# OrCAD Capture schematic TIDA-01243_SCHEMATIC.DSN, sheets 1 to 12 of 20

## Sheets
1 PAGE20_PCB_FAB_NOTES: title: TIDA-01243: PCB Fab Notes; rev: 2; company: Texas Instruments, CIS/ICP
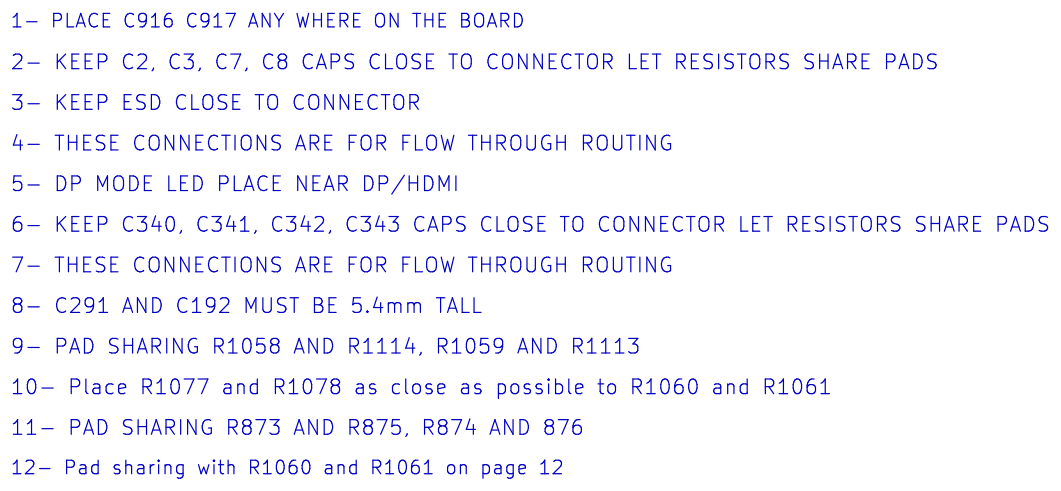
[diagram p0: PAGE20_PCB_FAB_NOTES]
2 PAGE01_EMPTY: title: TIDA-01243 Schematic
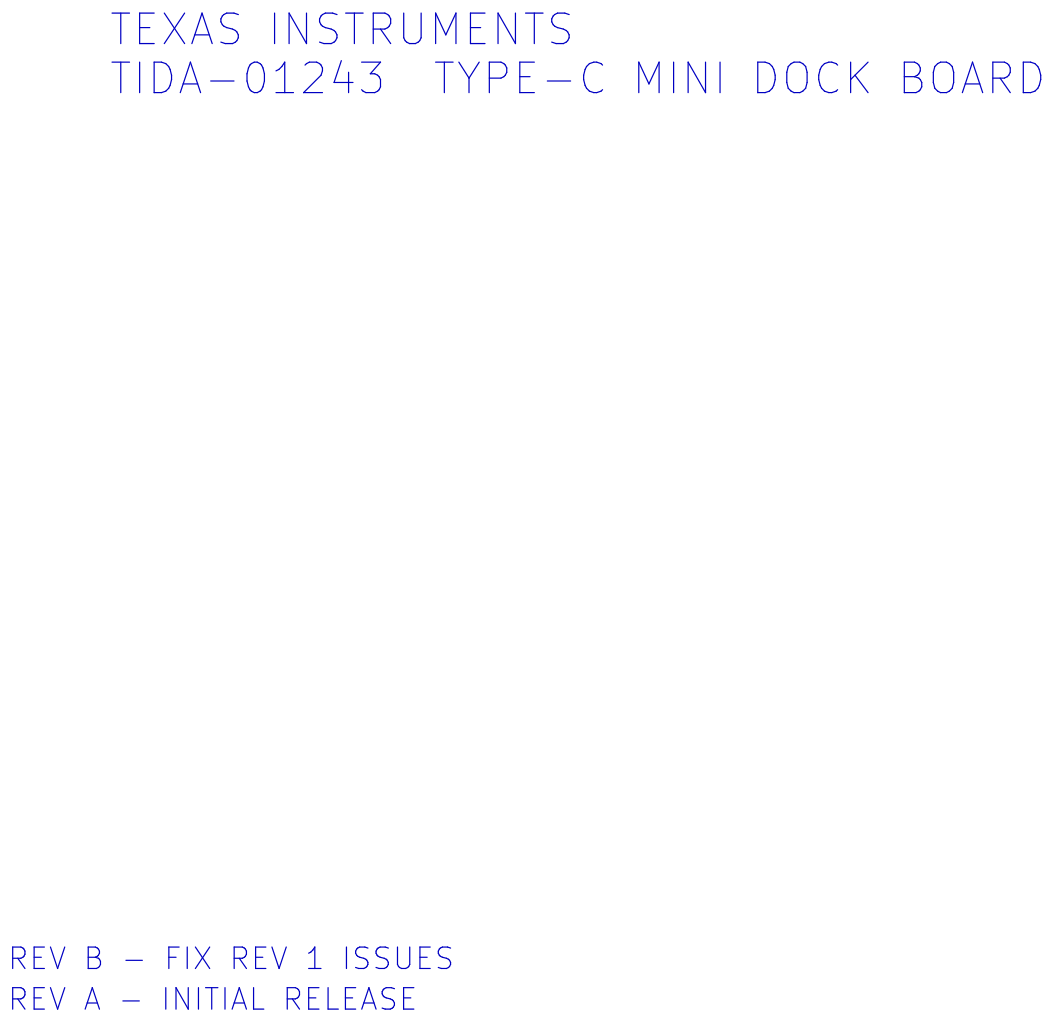
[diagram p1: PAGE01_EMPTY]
3 PAGE02_POWER: size B; title: TIDA-01243: POWER; rev: B
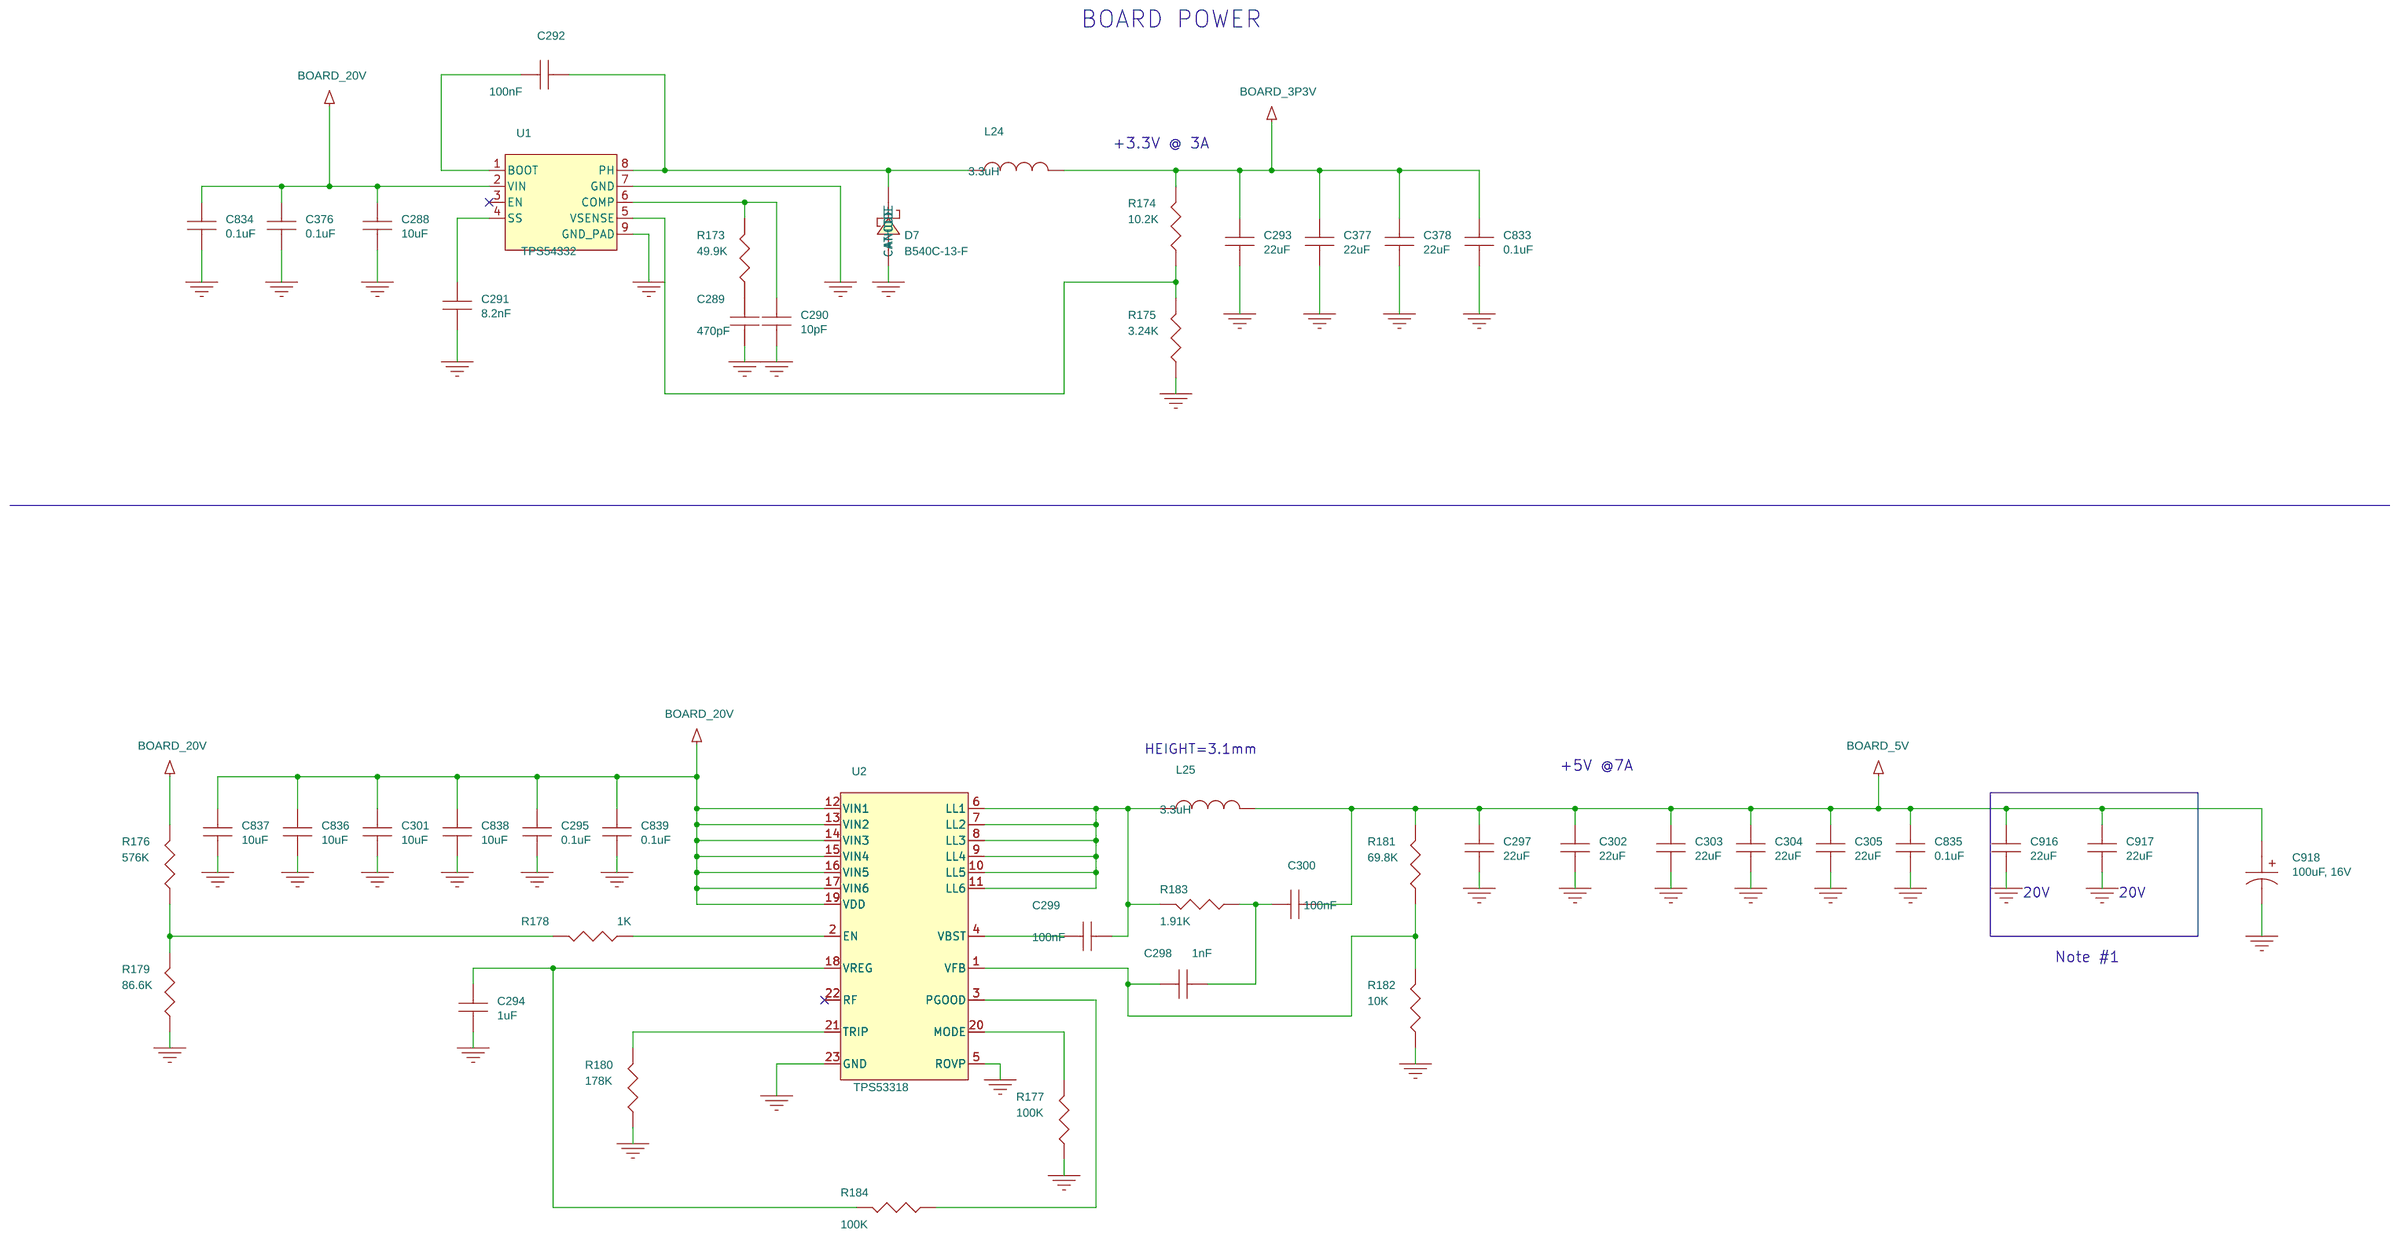
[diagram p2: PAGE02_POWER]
4 PAGE03_POWER2: size B; title: TIDA-01243: POWER2; rev: B
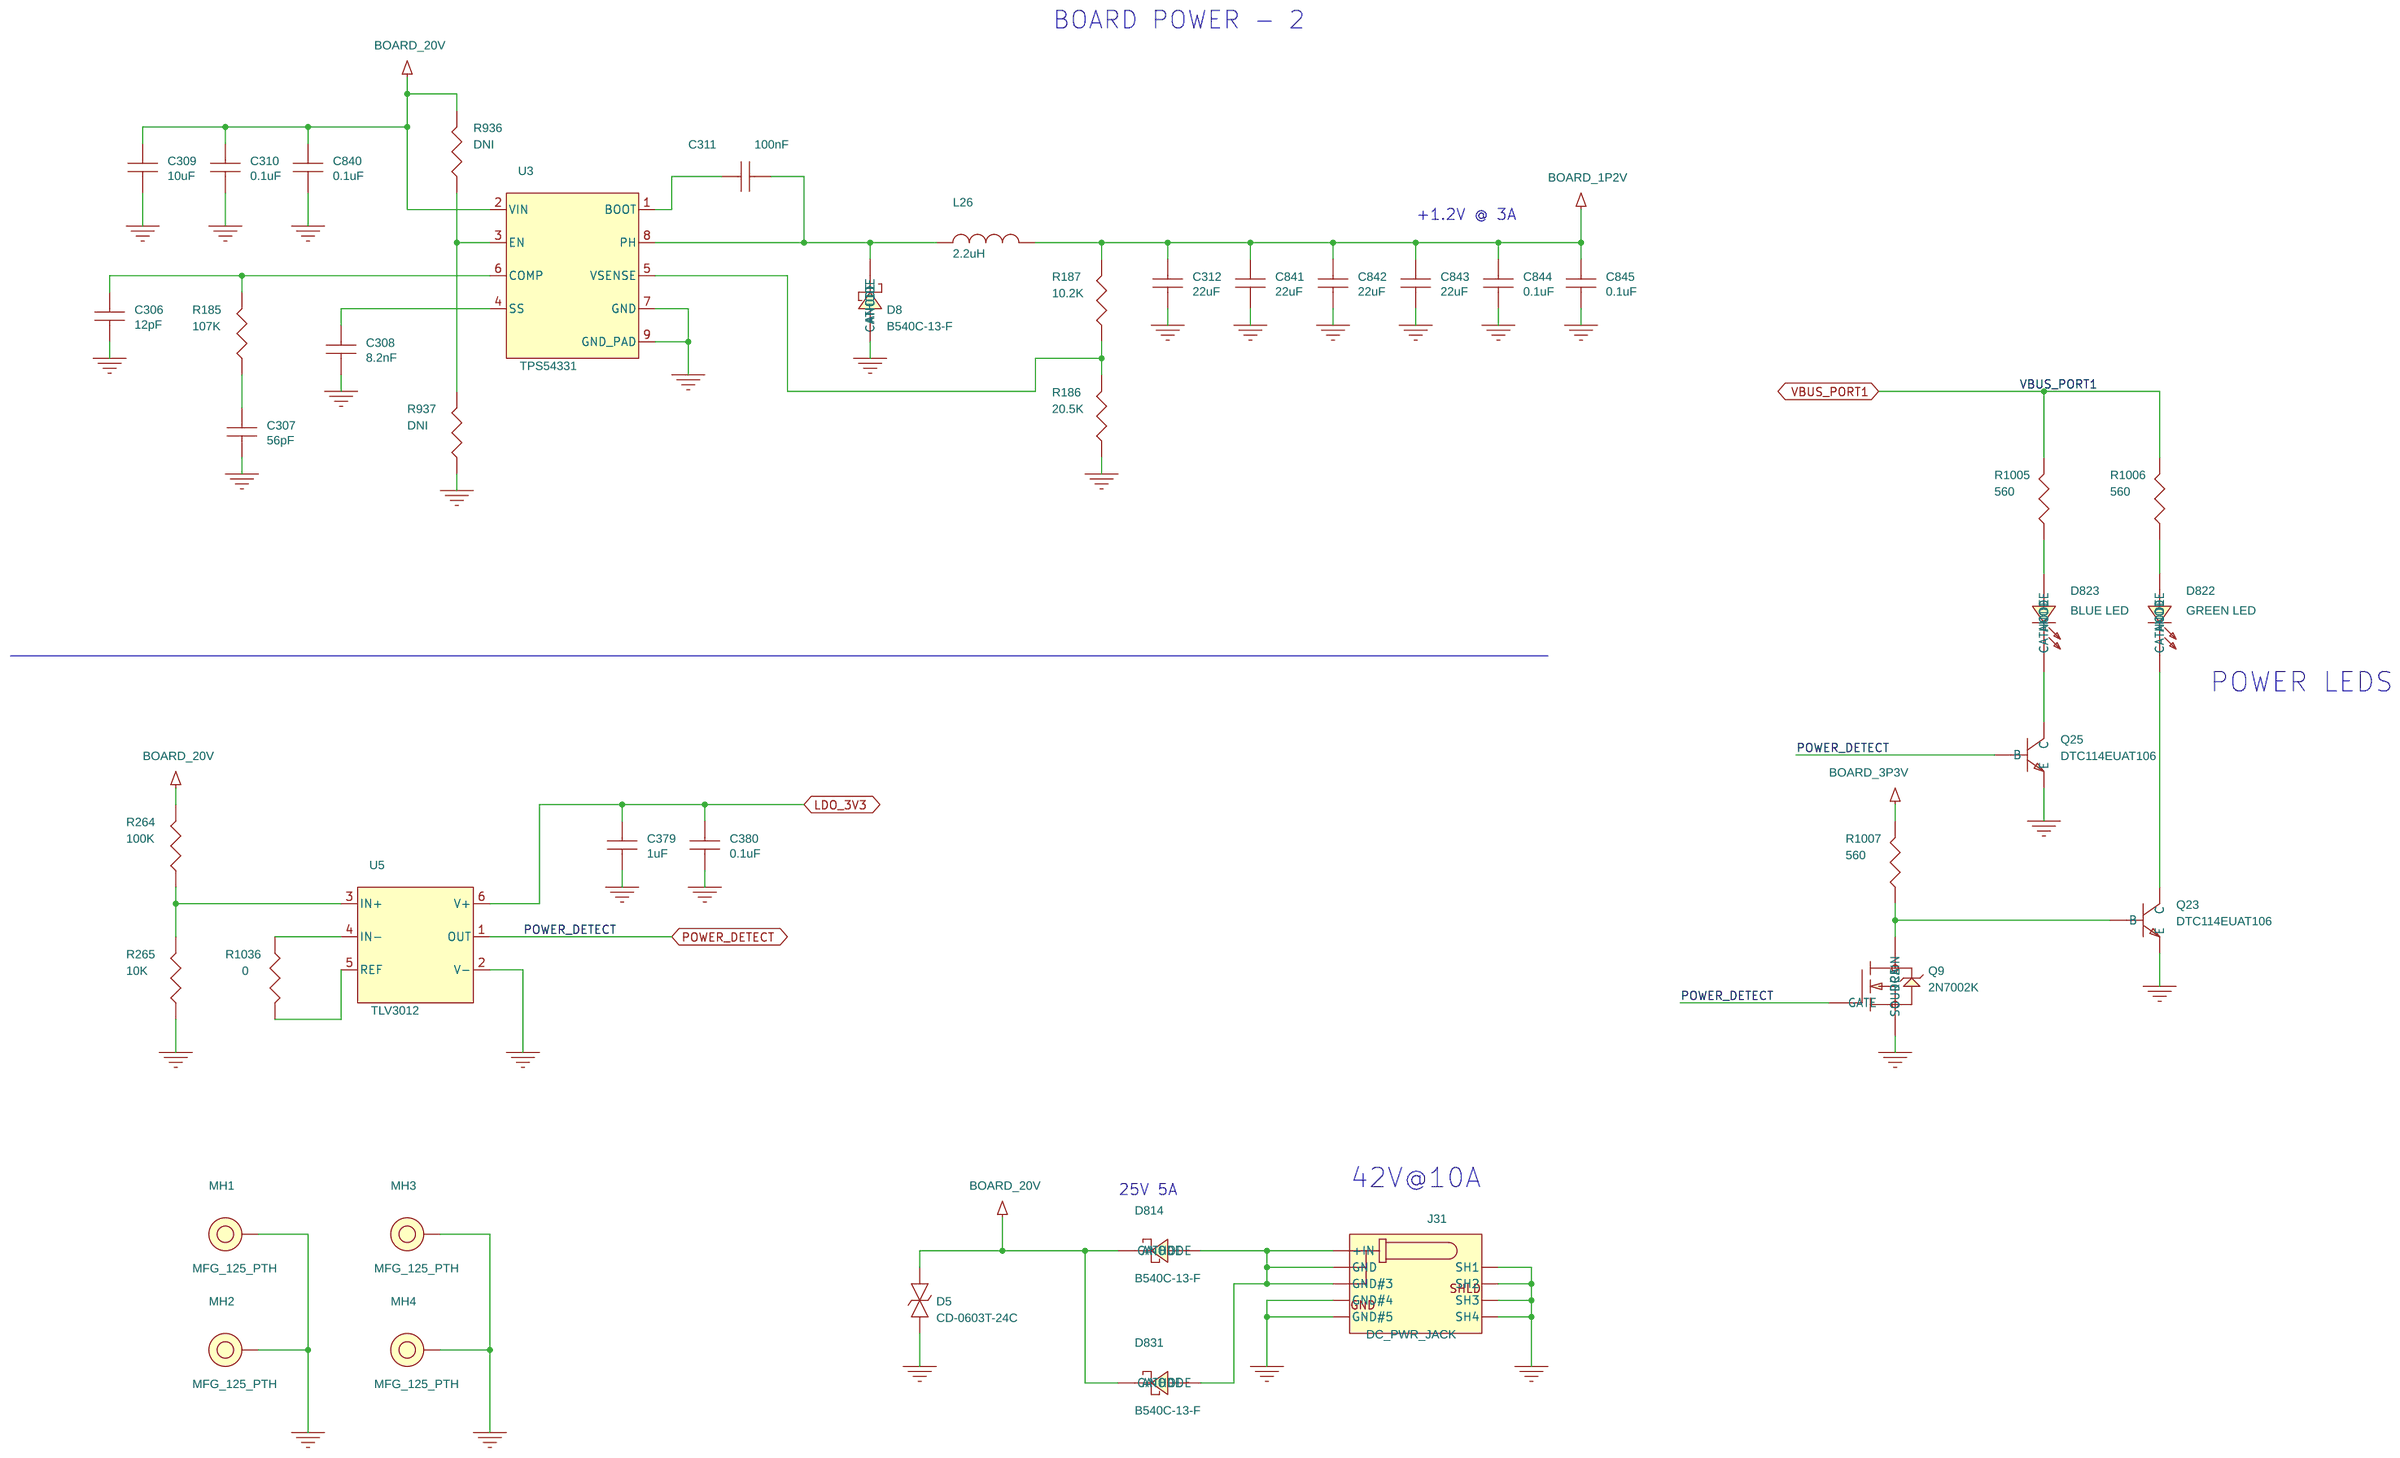
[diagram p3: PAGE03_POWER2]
5 PAGE05_UPSTREAM_TPS65986: size B; title: TIDA-01243: UPSTREAM TPS65986; rev: B
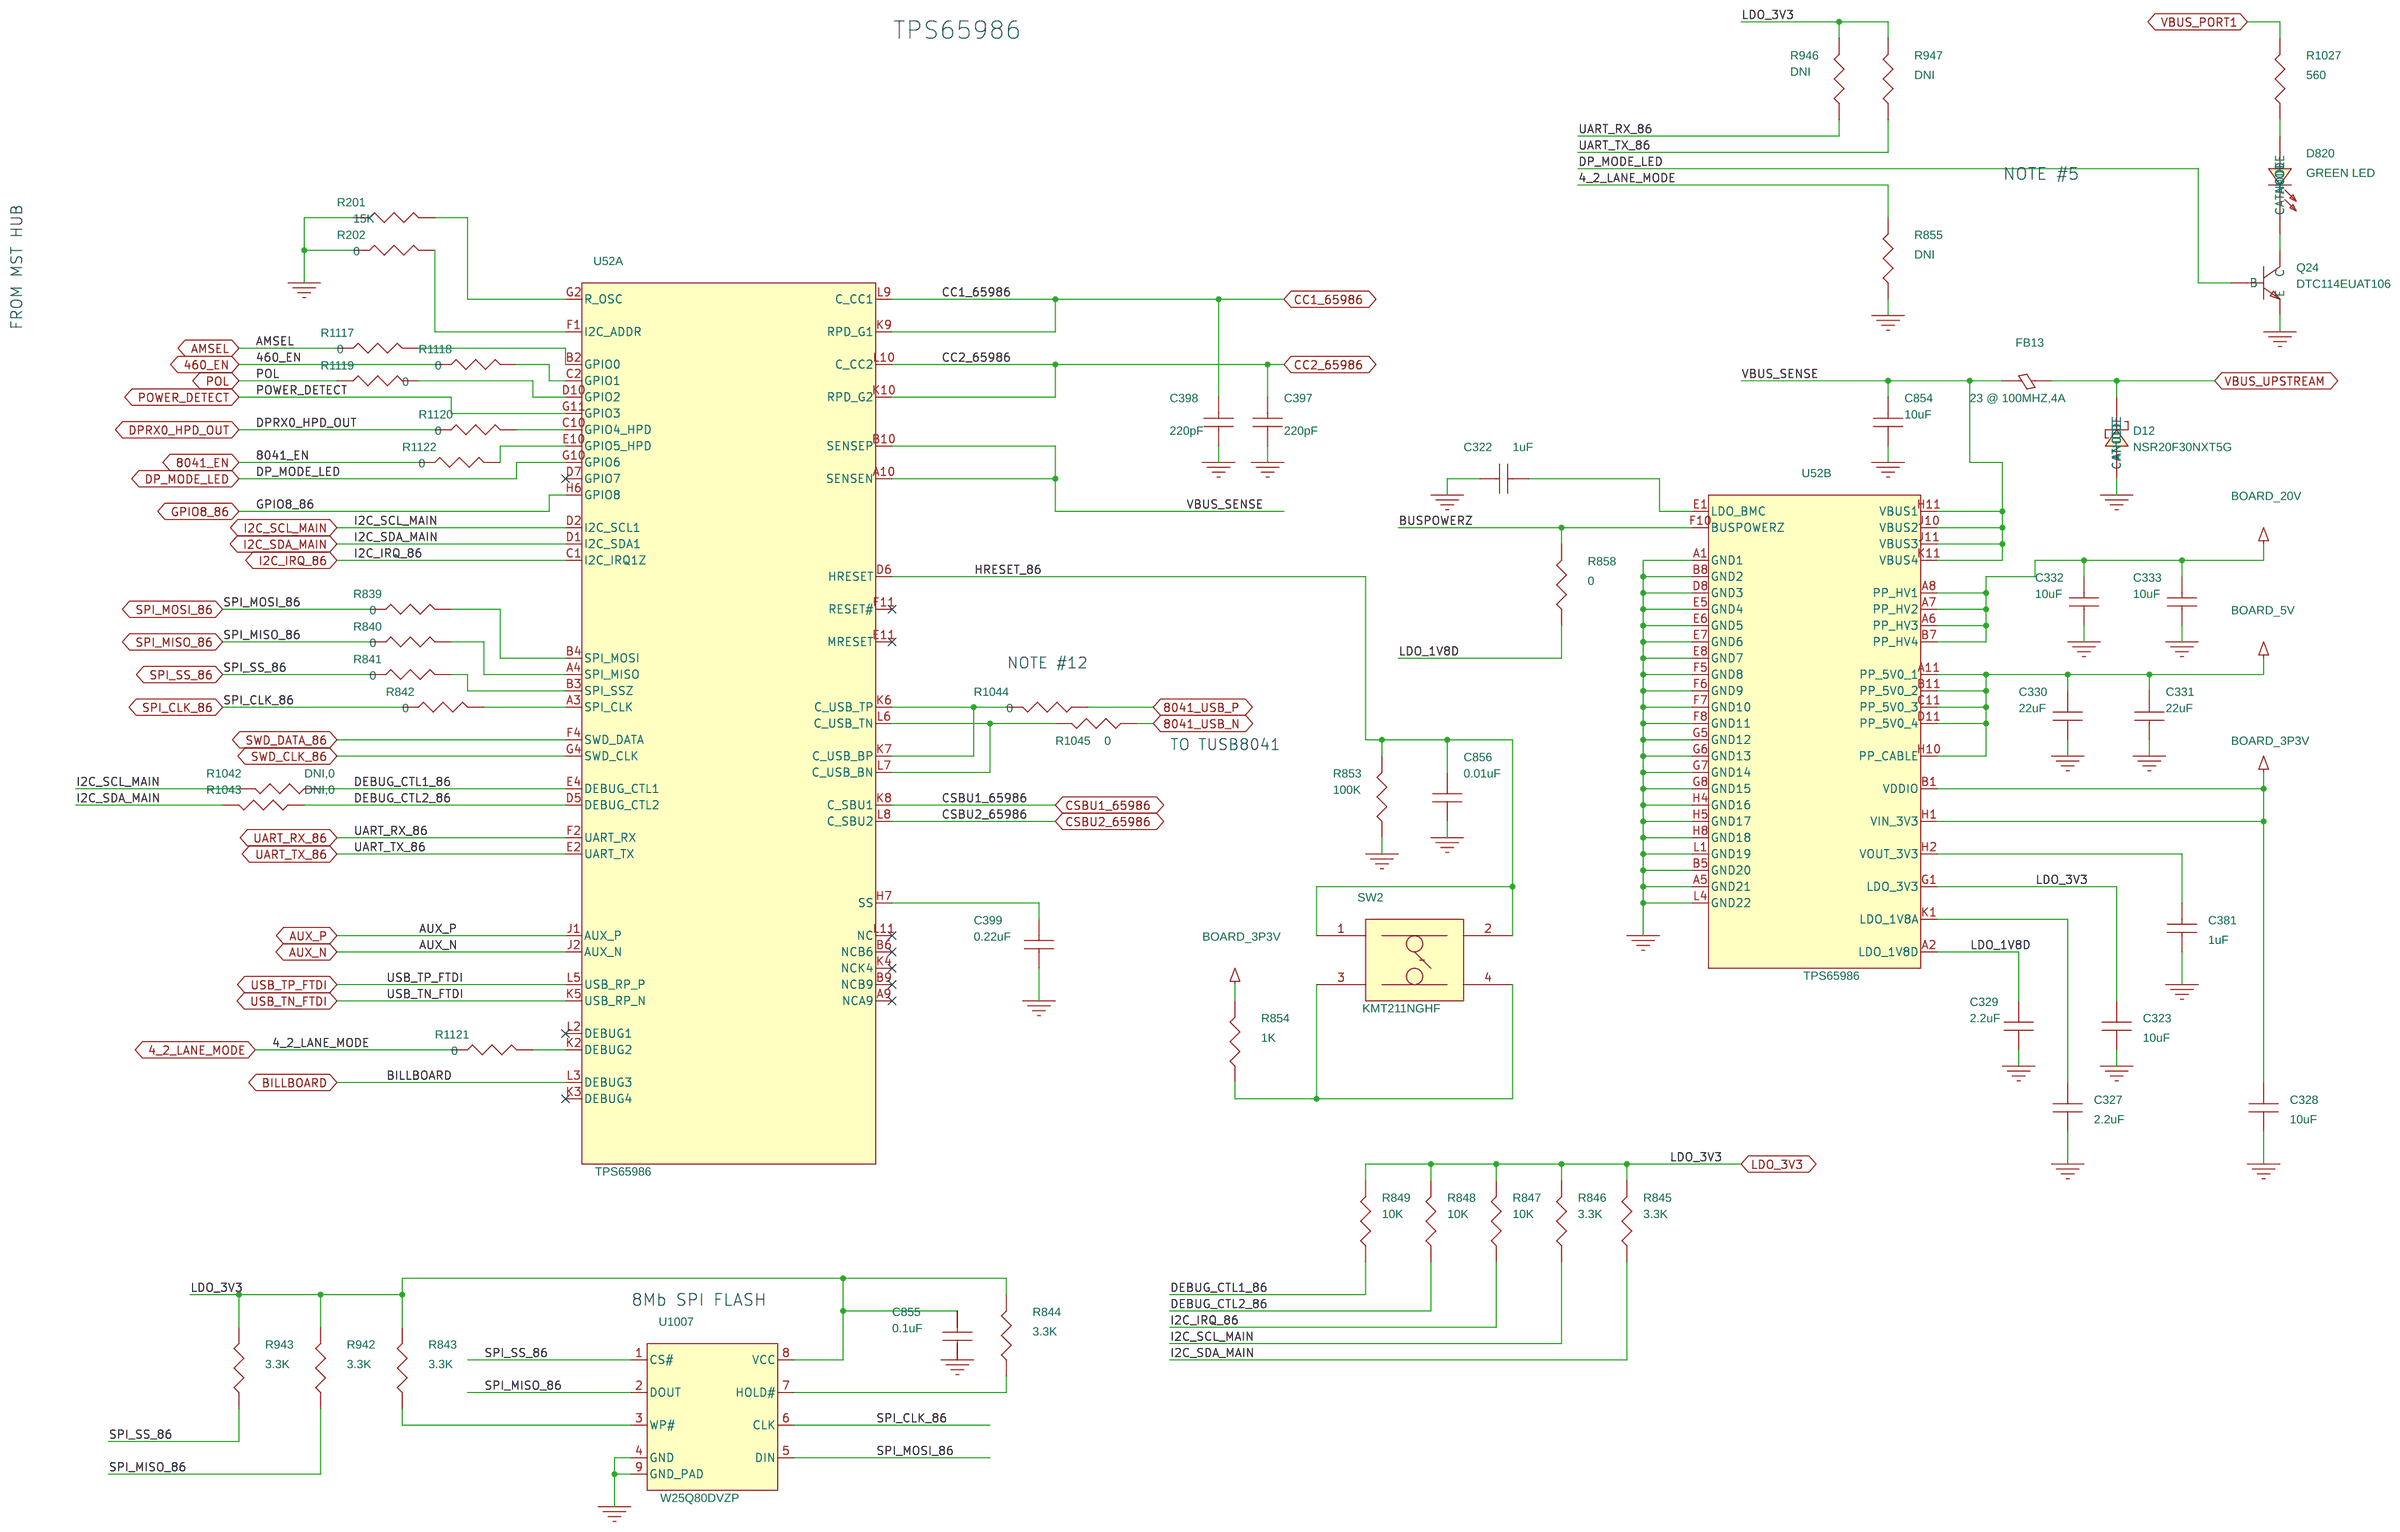
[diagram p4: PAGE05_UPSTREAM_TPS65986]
6 PAGE06_TUSB8041: size B; title: TIDA-01243: TUSB8041; rev: B
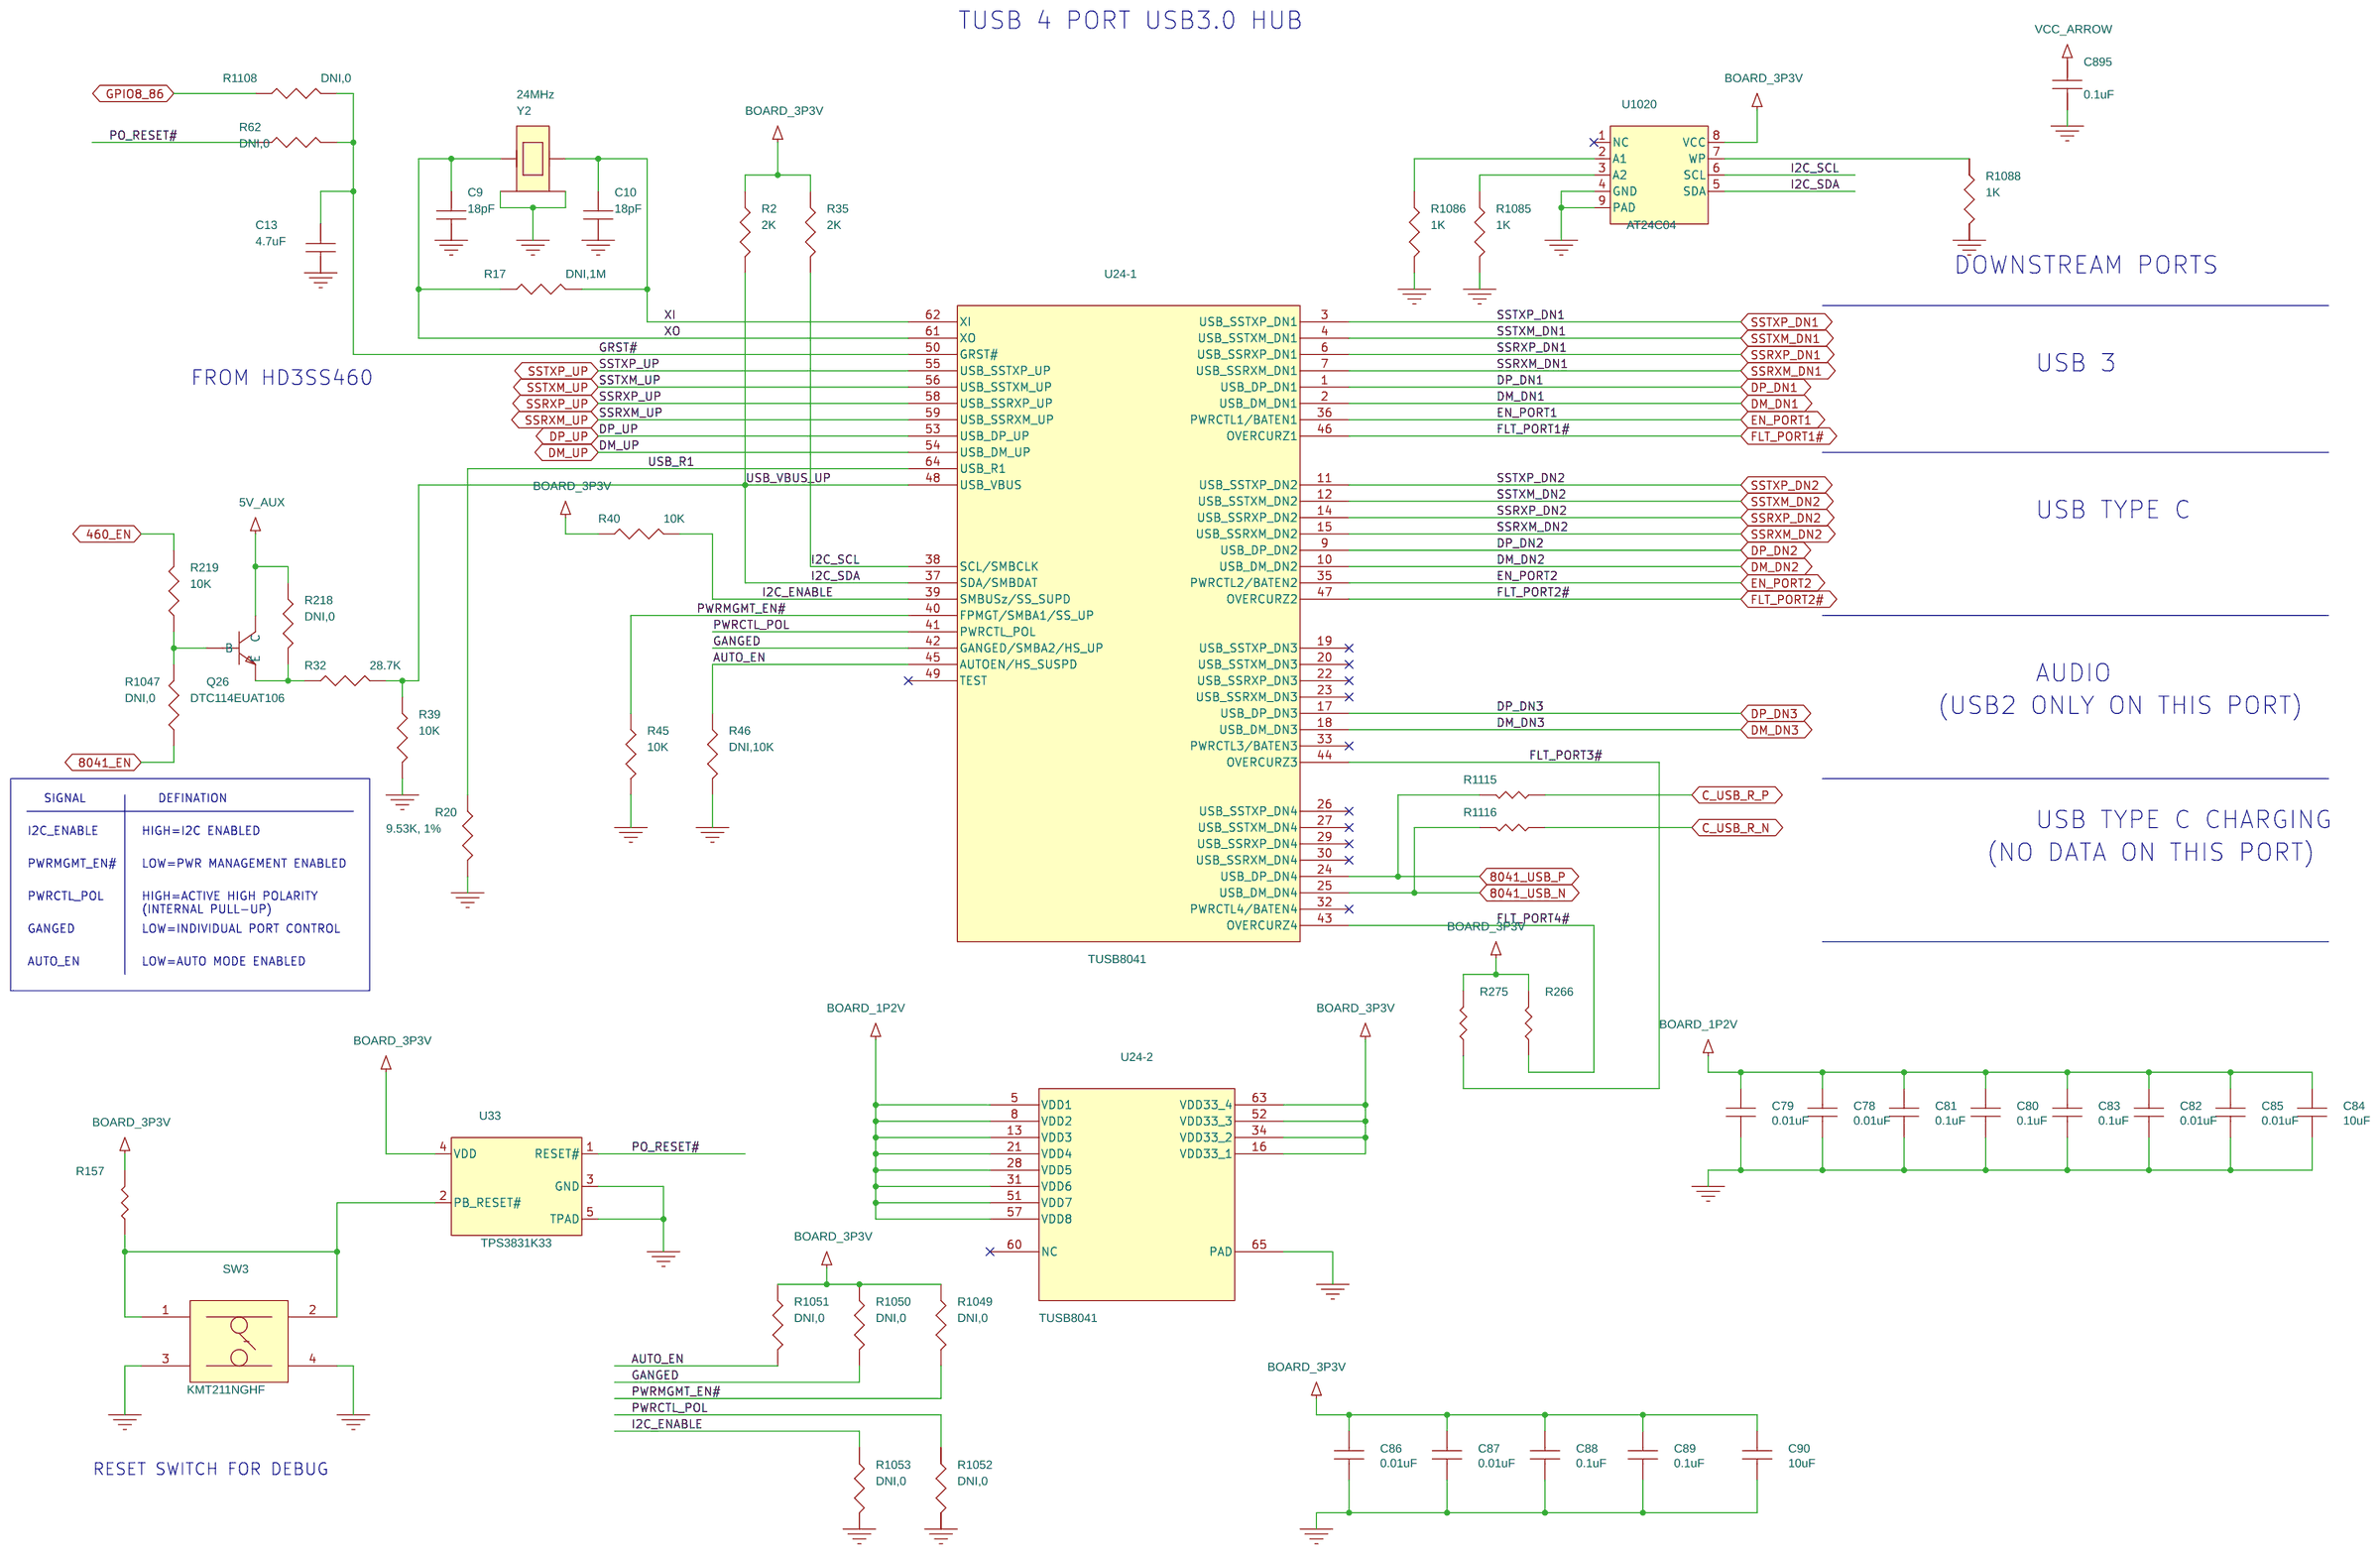
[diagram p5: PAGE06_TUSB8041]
7 PAGE07_PORT1_USB3: size B; title: TIDA-01243: PORT1 USB3; rev: B
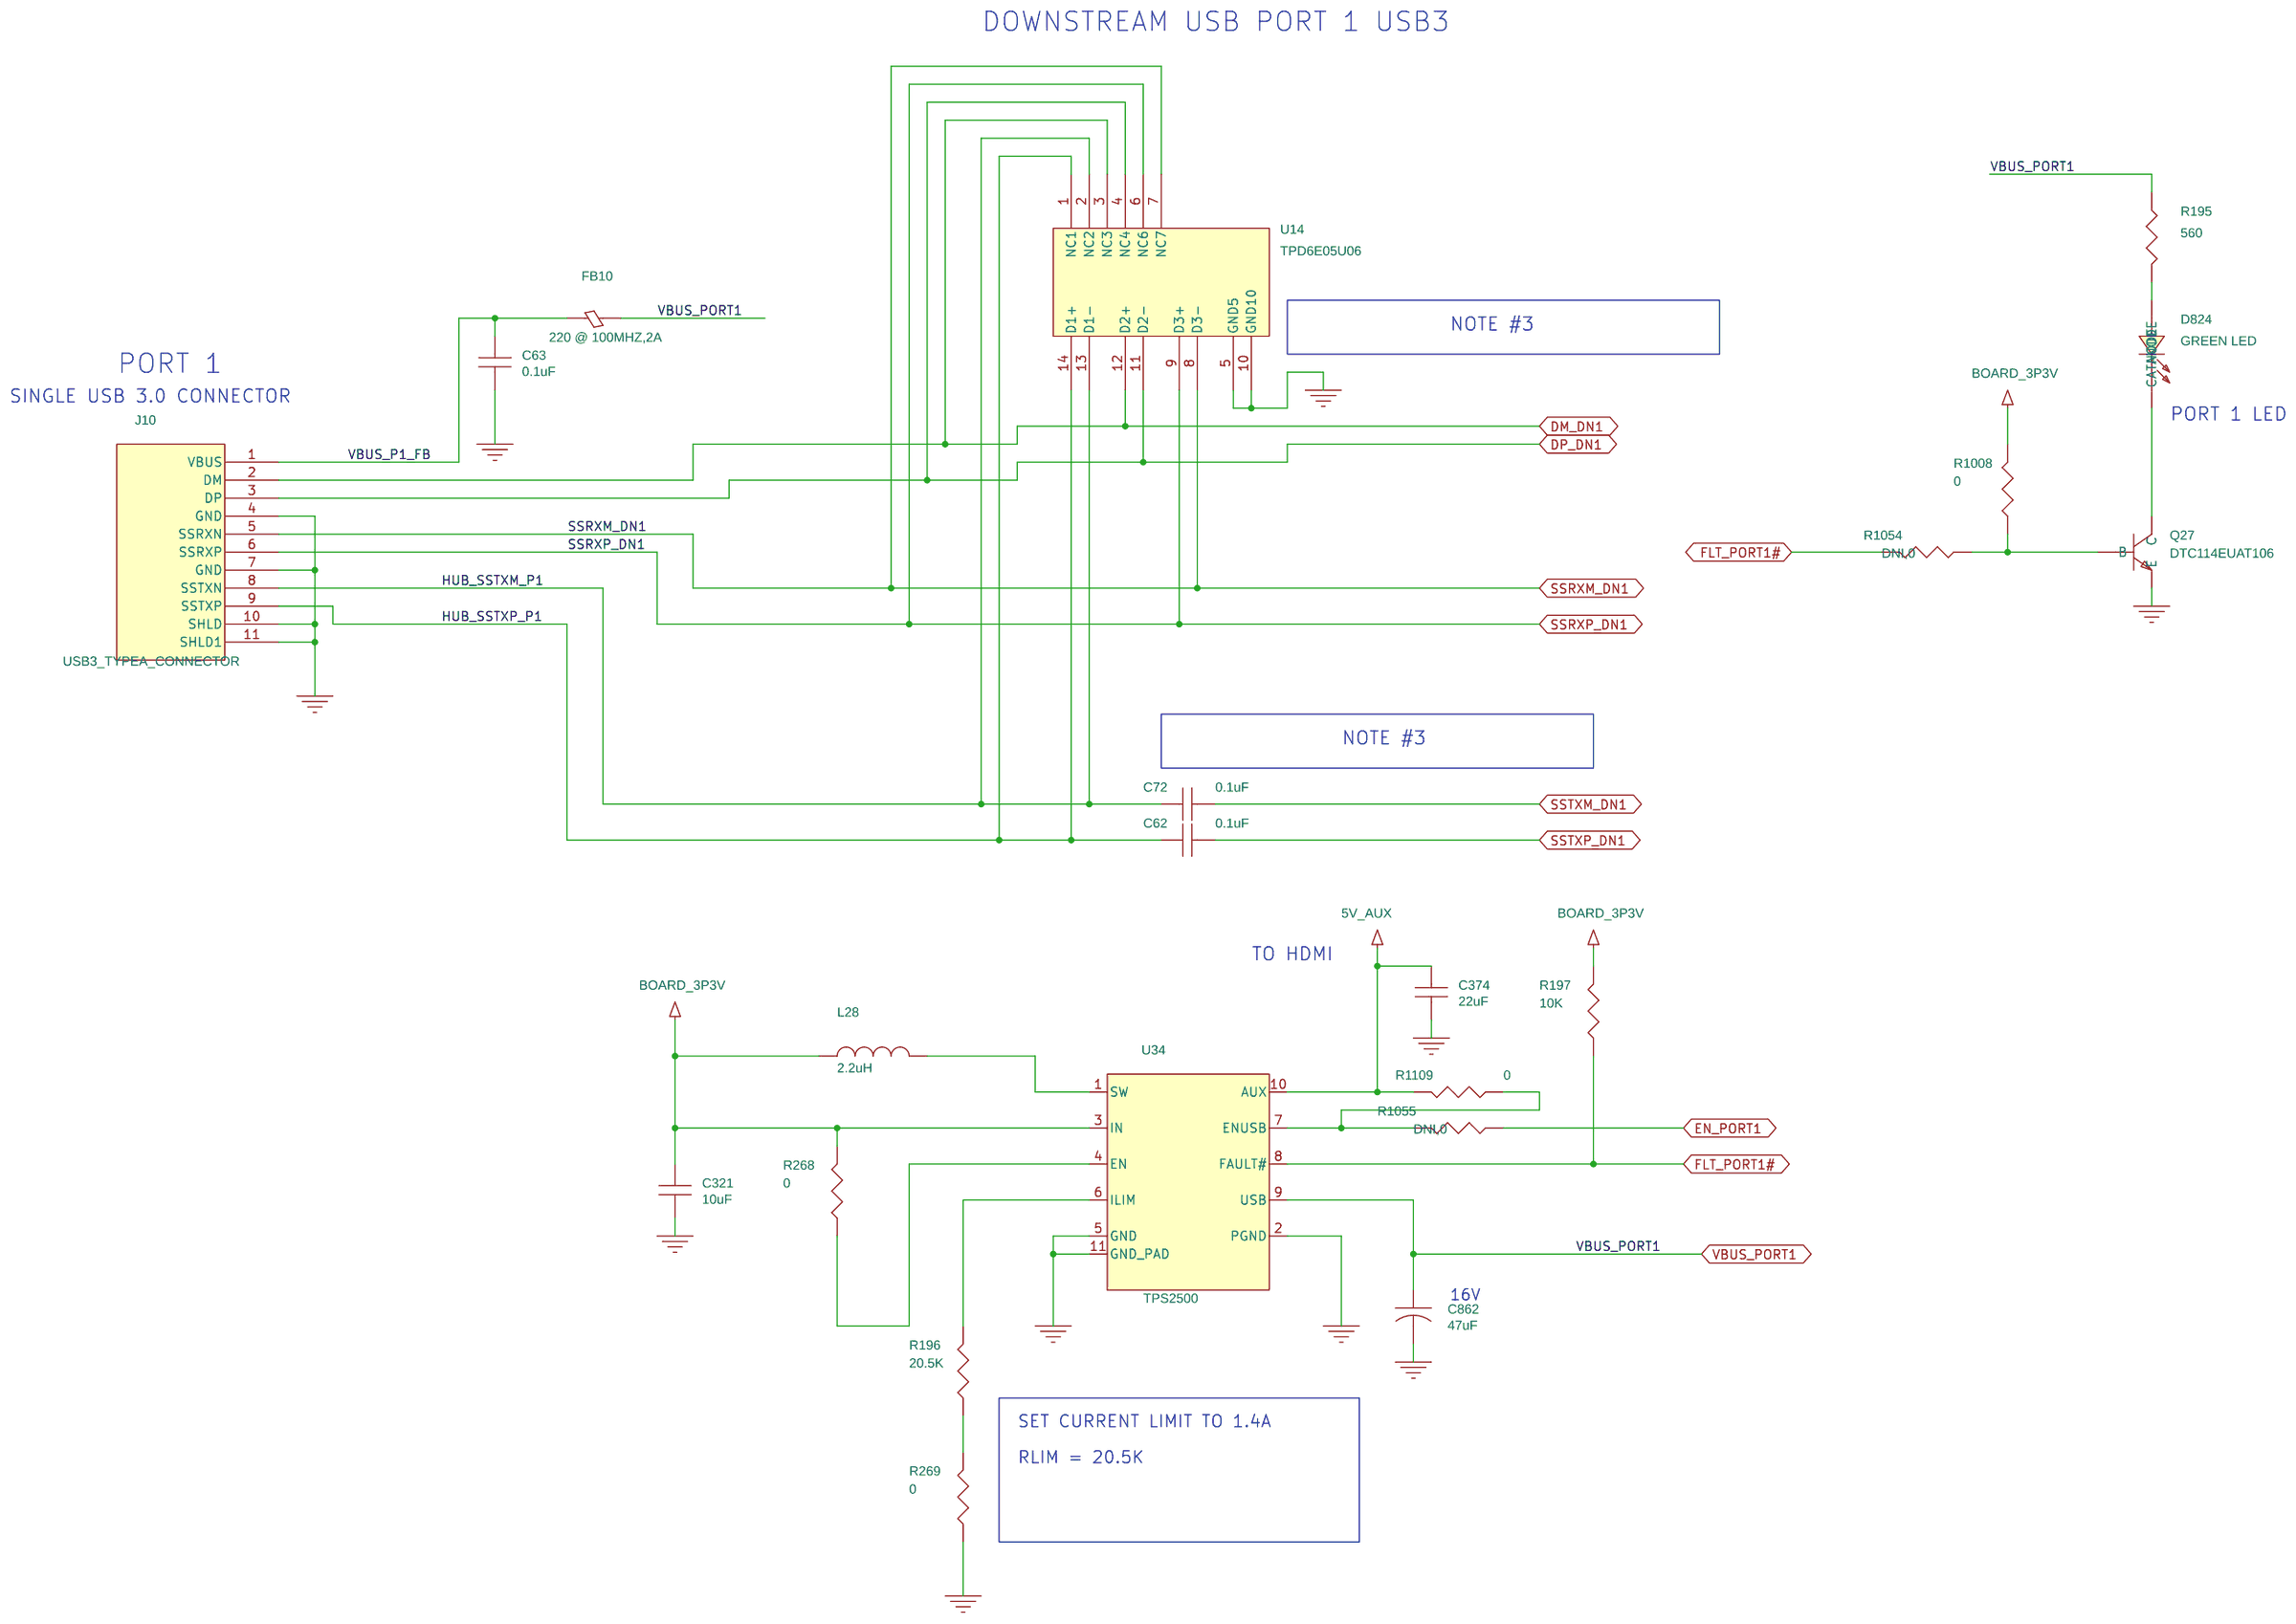
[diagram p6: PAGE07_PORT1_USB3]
8 PAGE08_PORT2_USBC: size B; title: TIDA-01243: PORT 2 USBC; rev: B
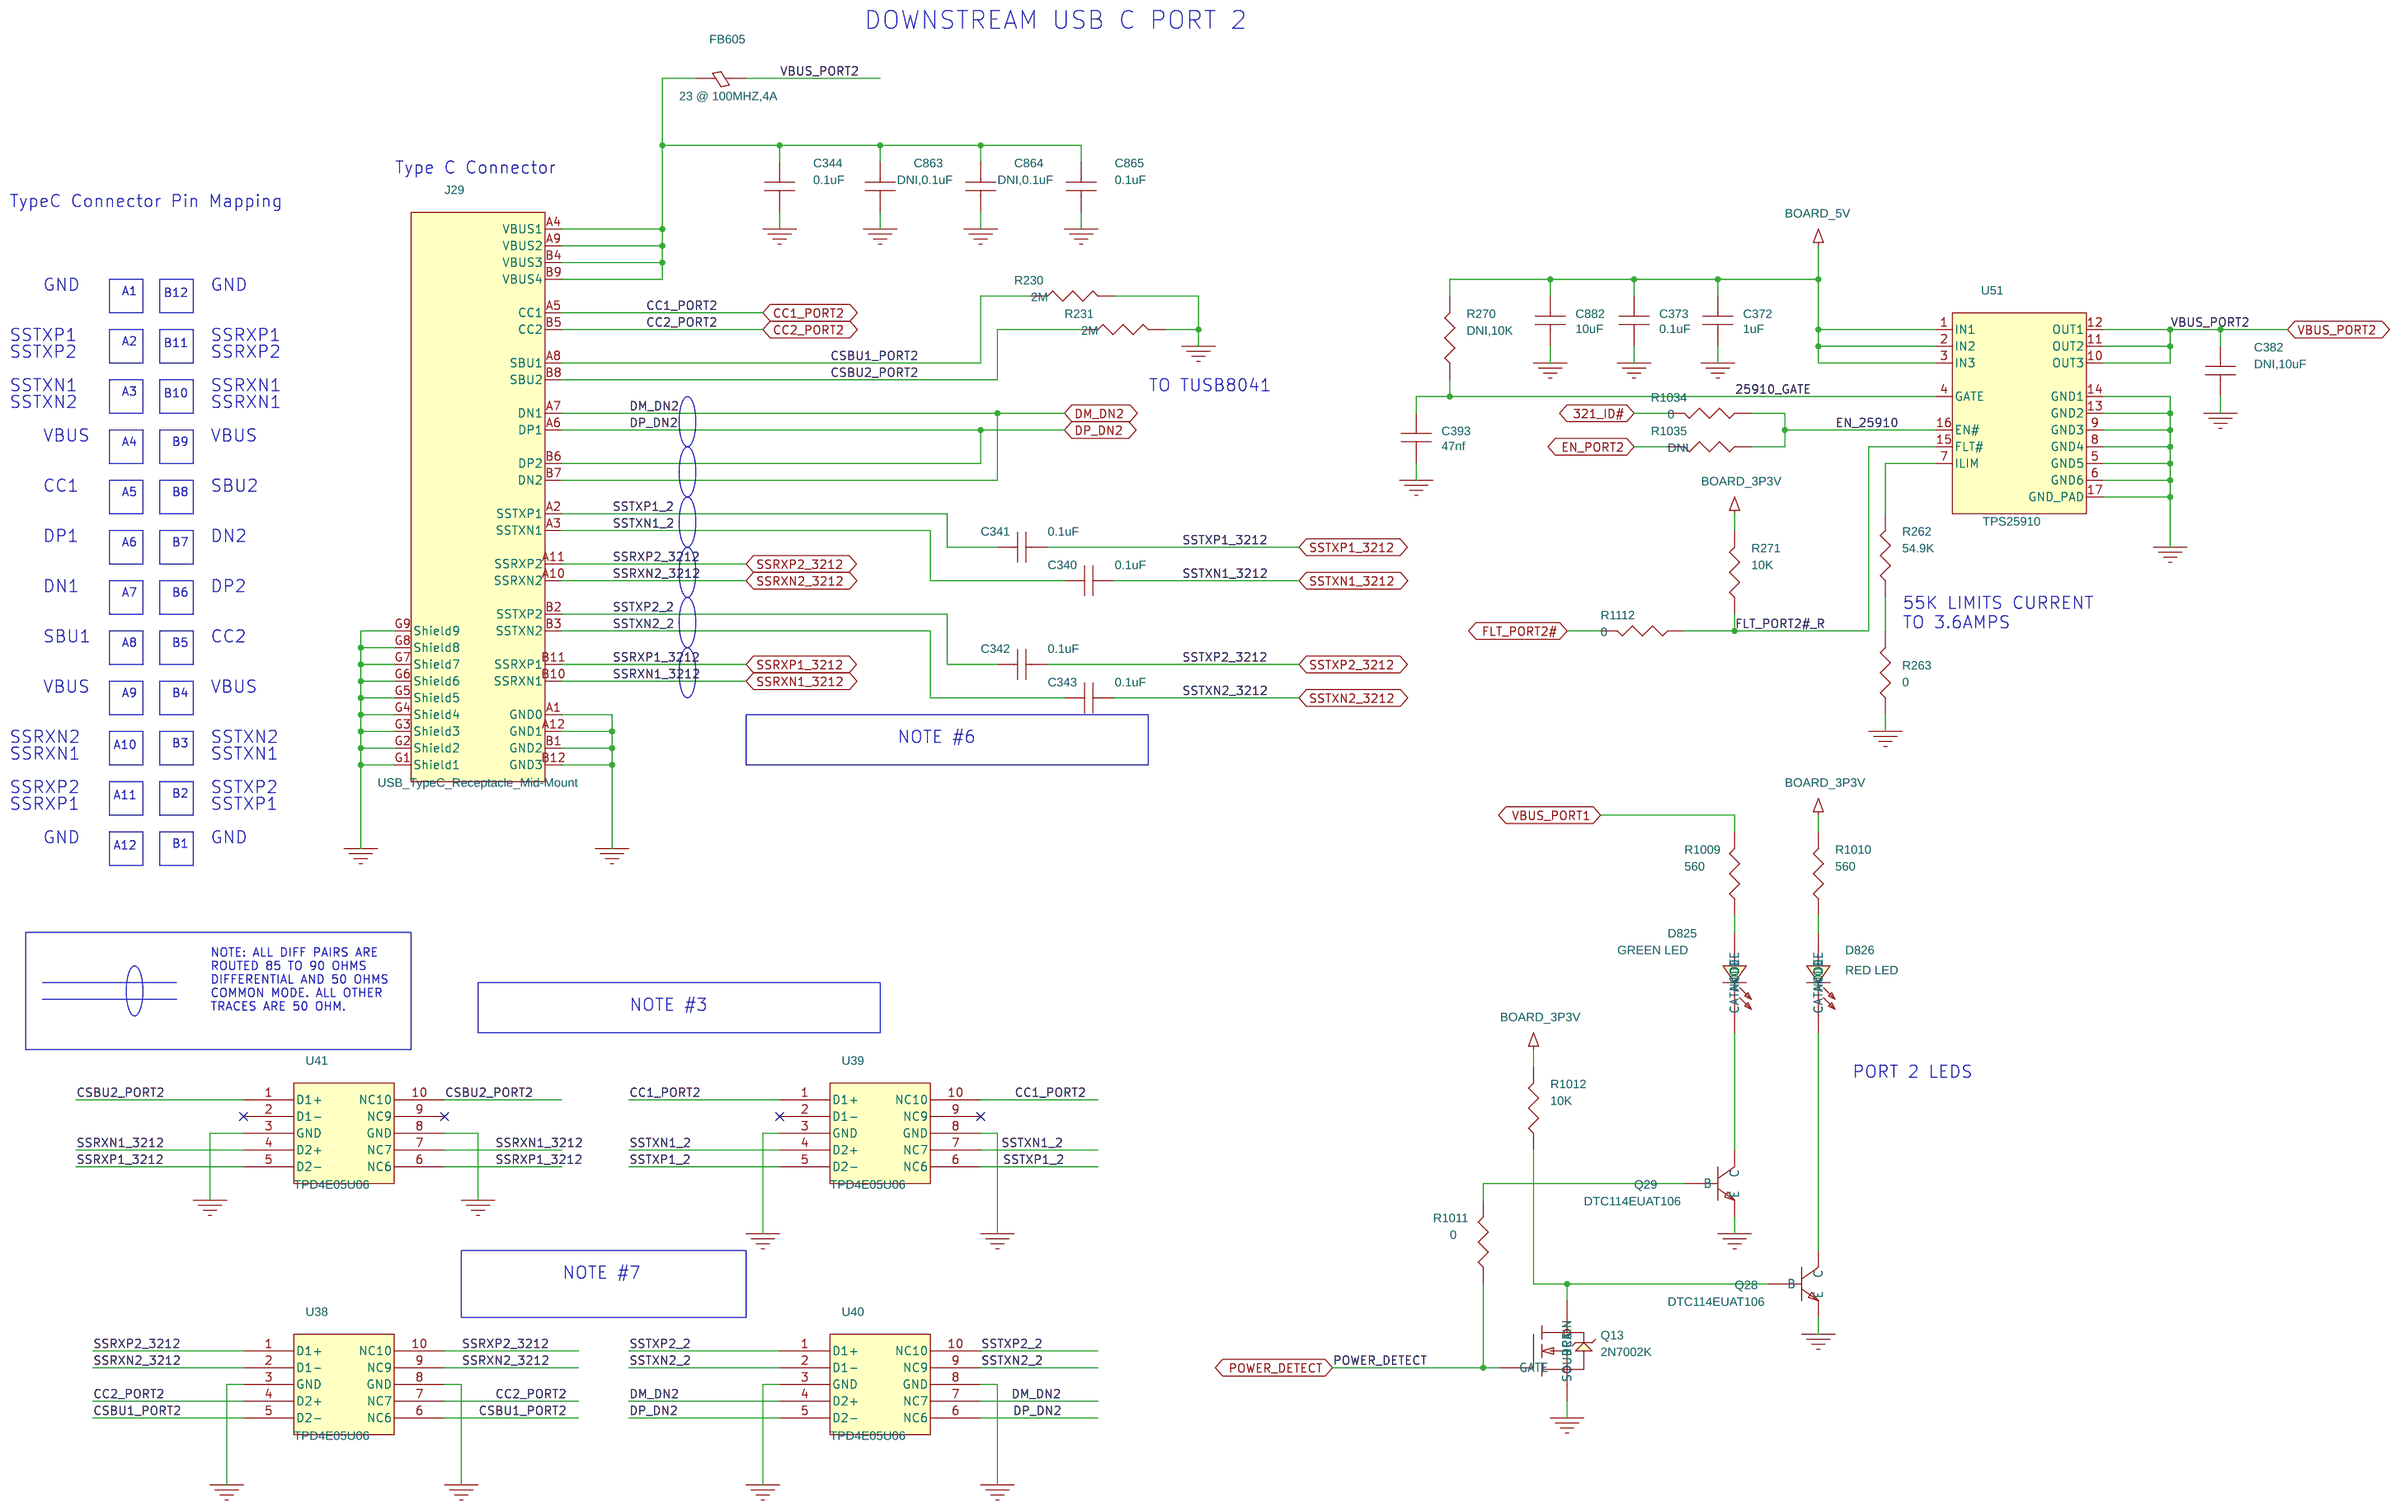
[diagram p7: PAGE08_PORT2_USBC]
9 PAGE09_PORT2_USBC_2: size B; title: TIDA-01243: PORT2_USBC_2; rev: B
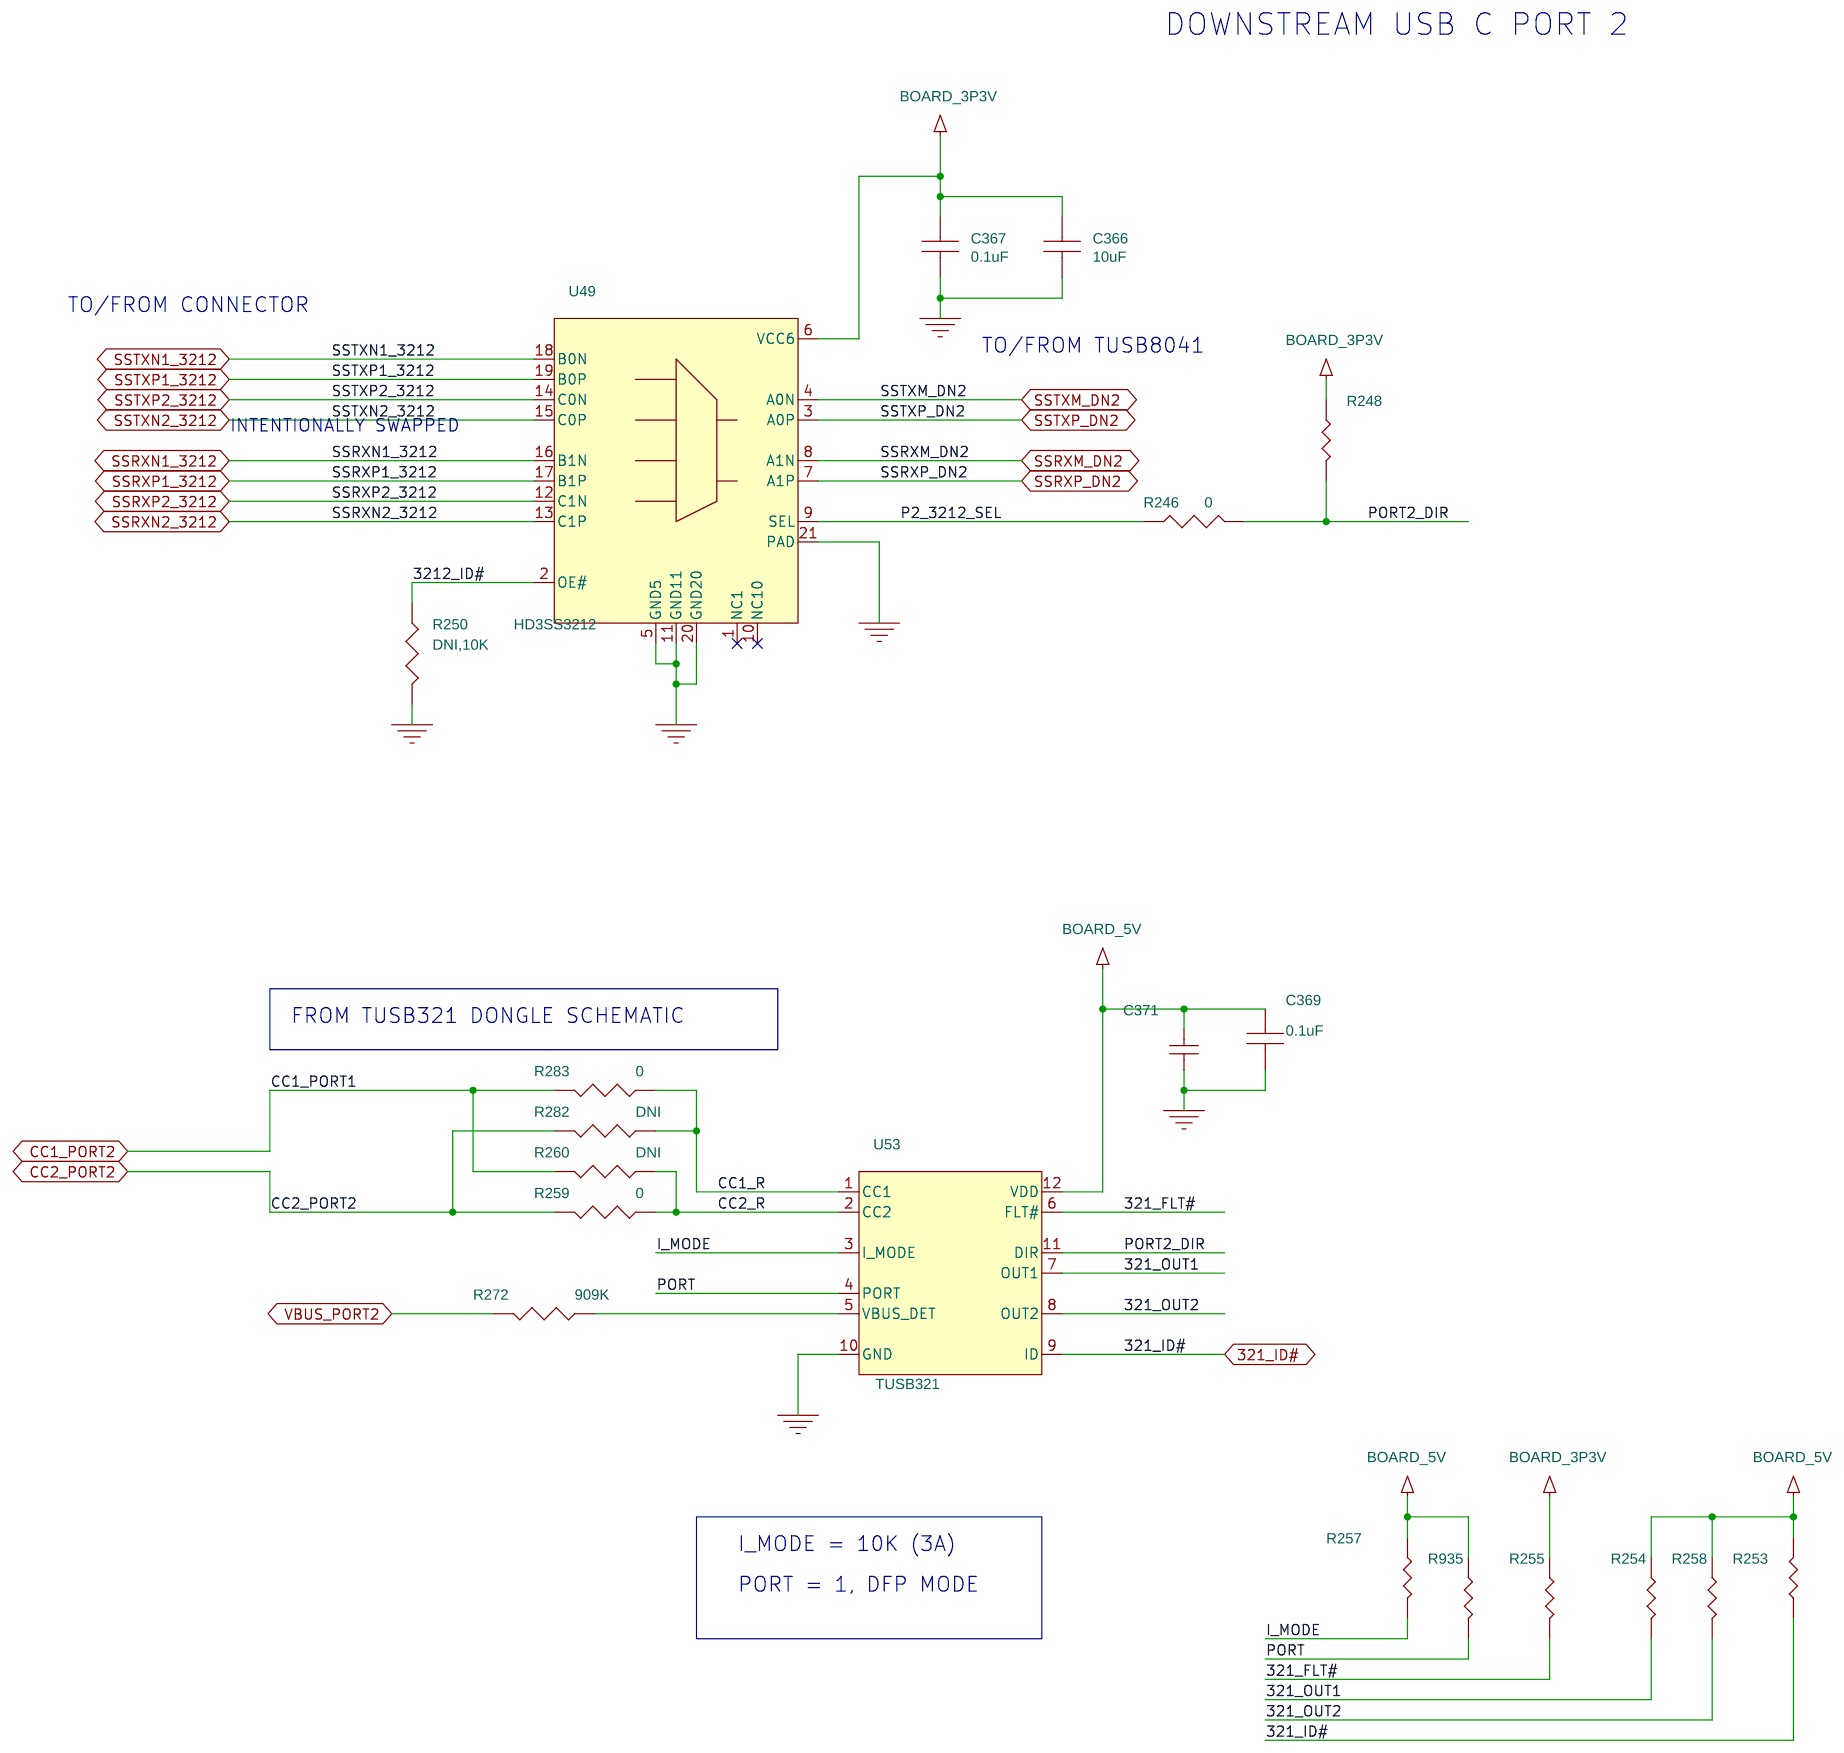
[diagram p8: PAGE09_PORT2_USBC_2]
10 PAGE10_PORT3_USB_AUDIO: size B; title: TIDA-01243: PORT3 USB AUDIO; rev: B
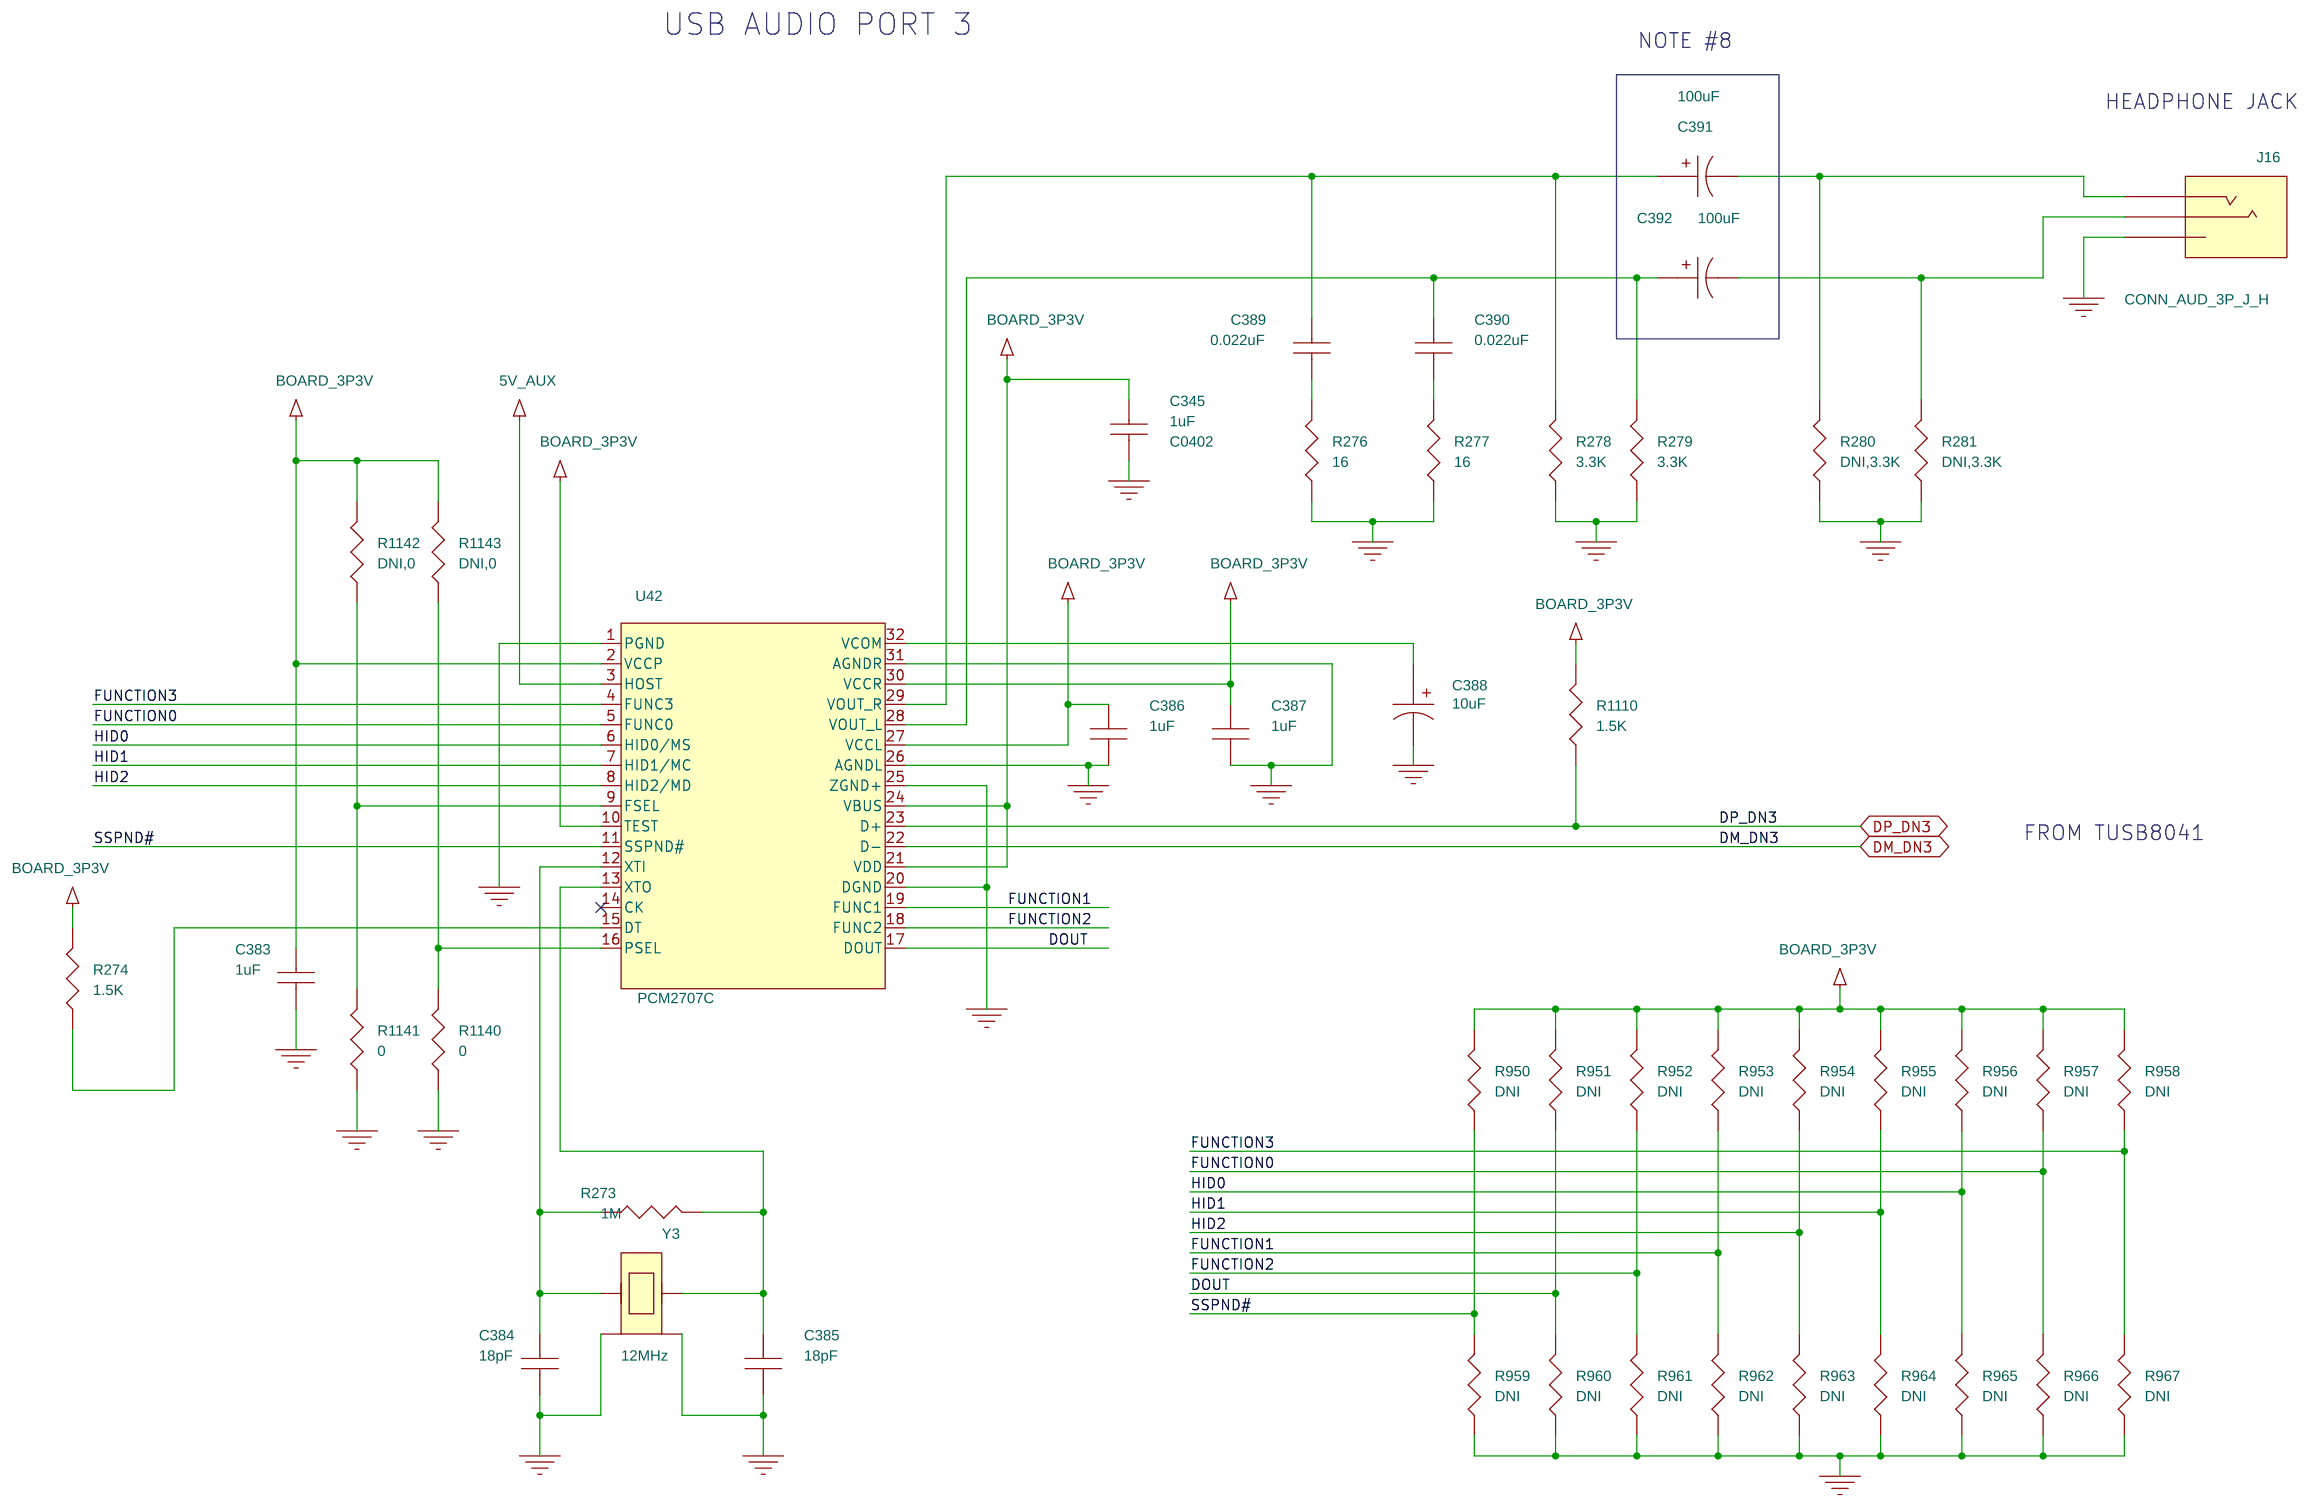
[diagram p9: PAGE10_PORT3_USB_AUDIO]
11 PAGE11_PORT4_USB_C_CHARGING: size B; title: TIDA-01243: PORT4_USBC_CHARGING; rev: B
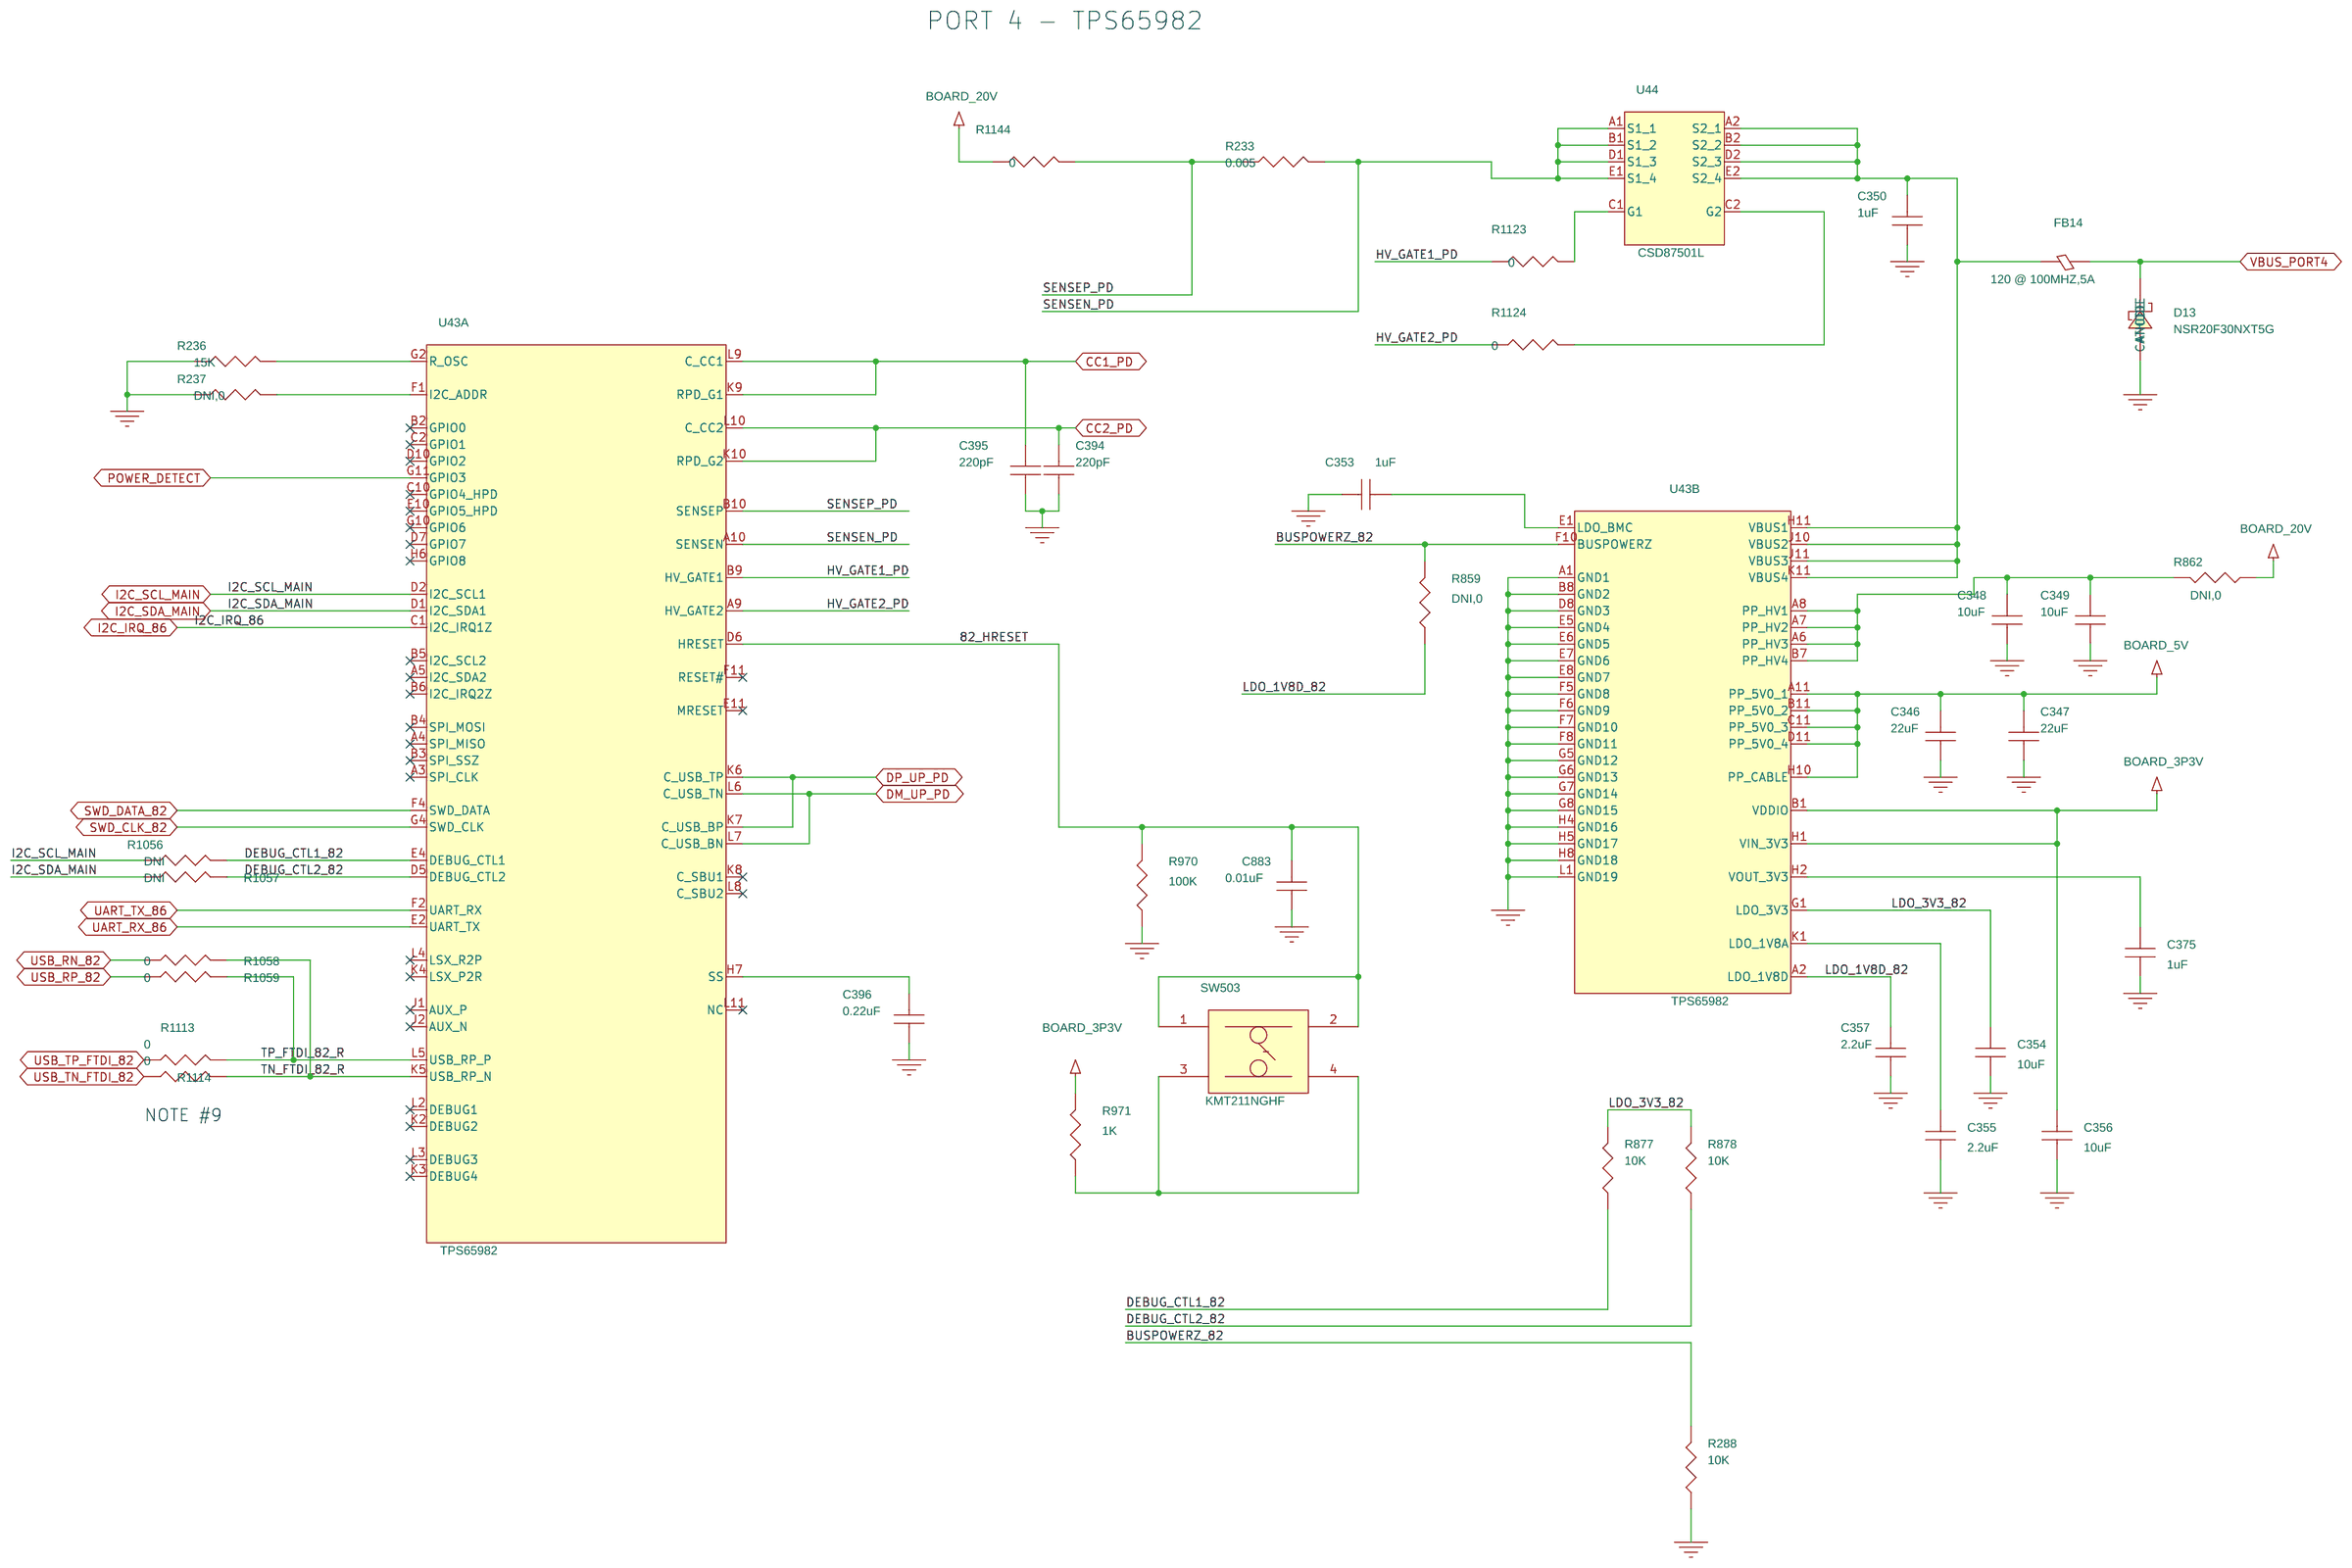
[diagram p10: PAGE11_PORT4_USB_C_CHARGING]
12 PAGE12_PORT4_USB_C_CON: size B; title: TIDA-01243: PORT4 USBC CON; rev: B
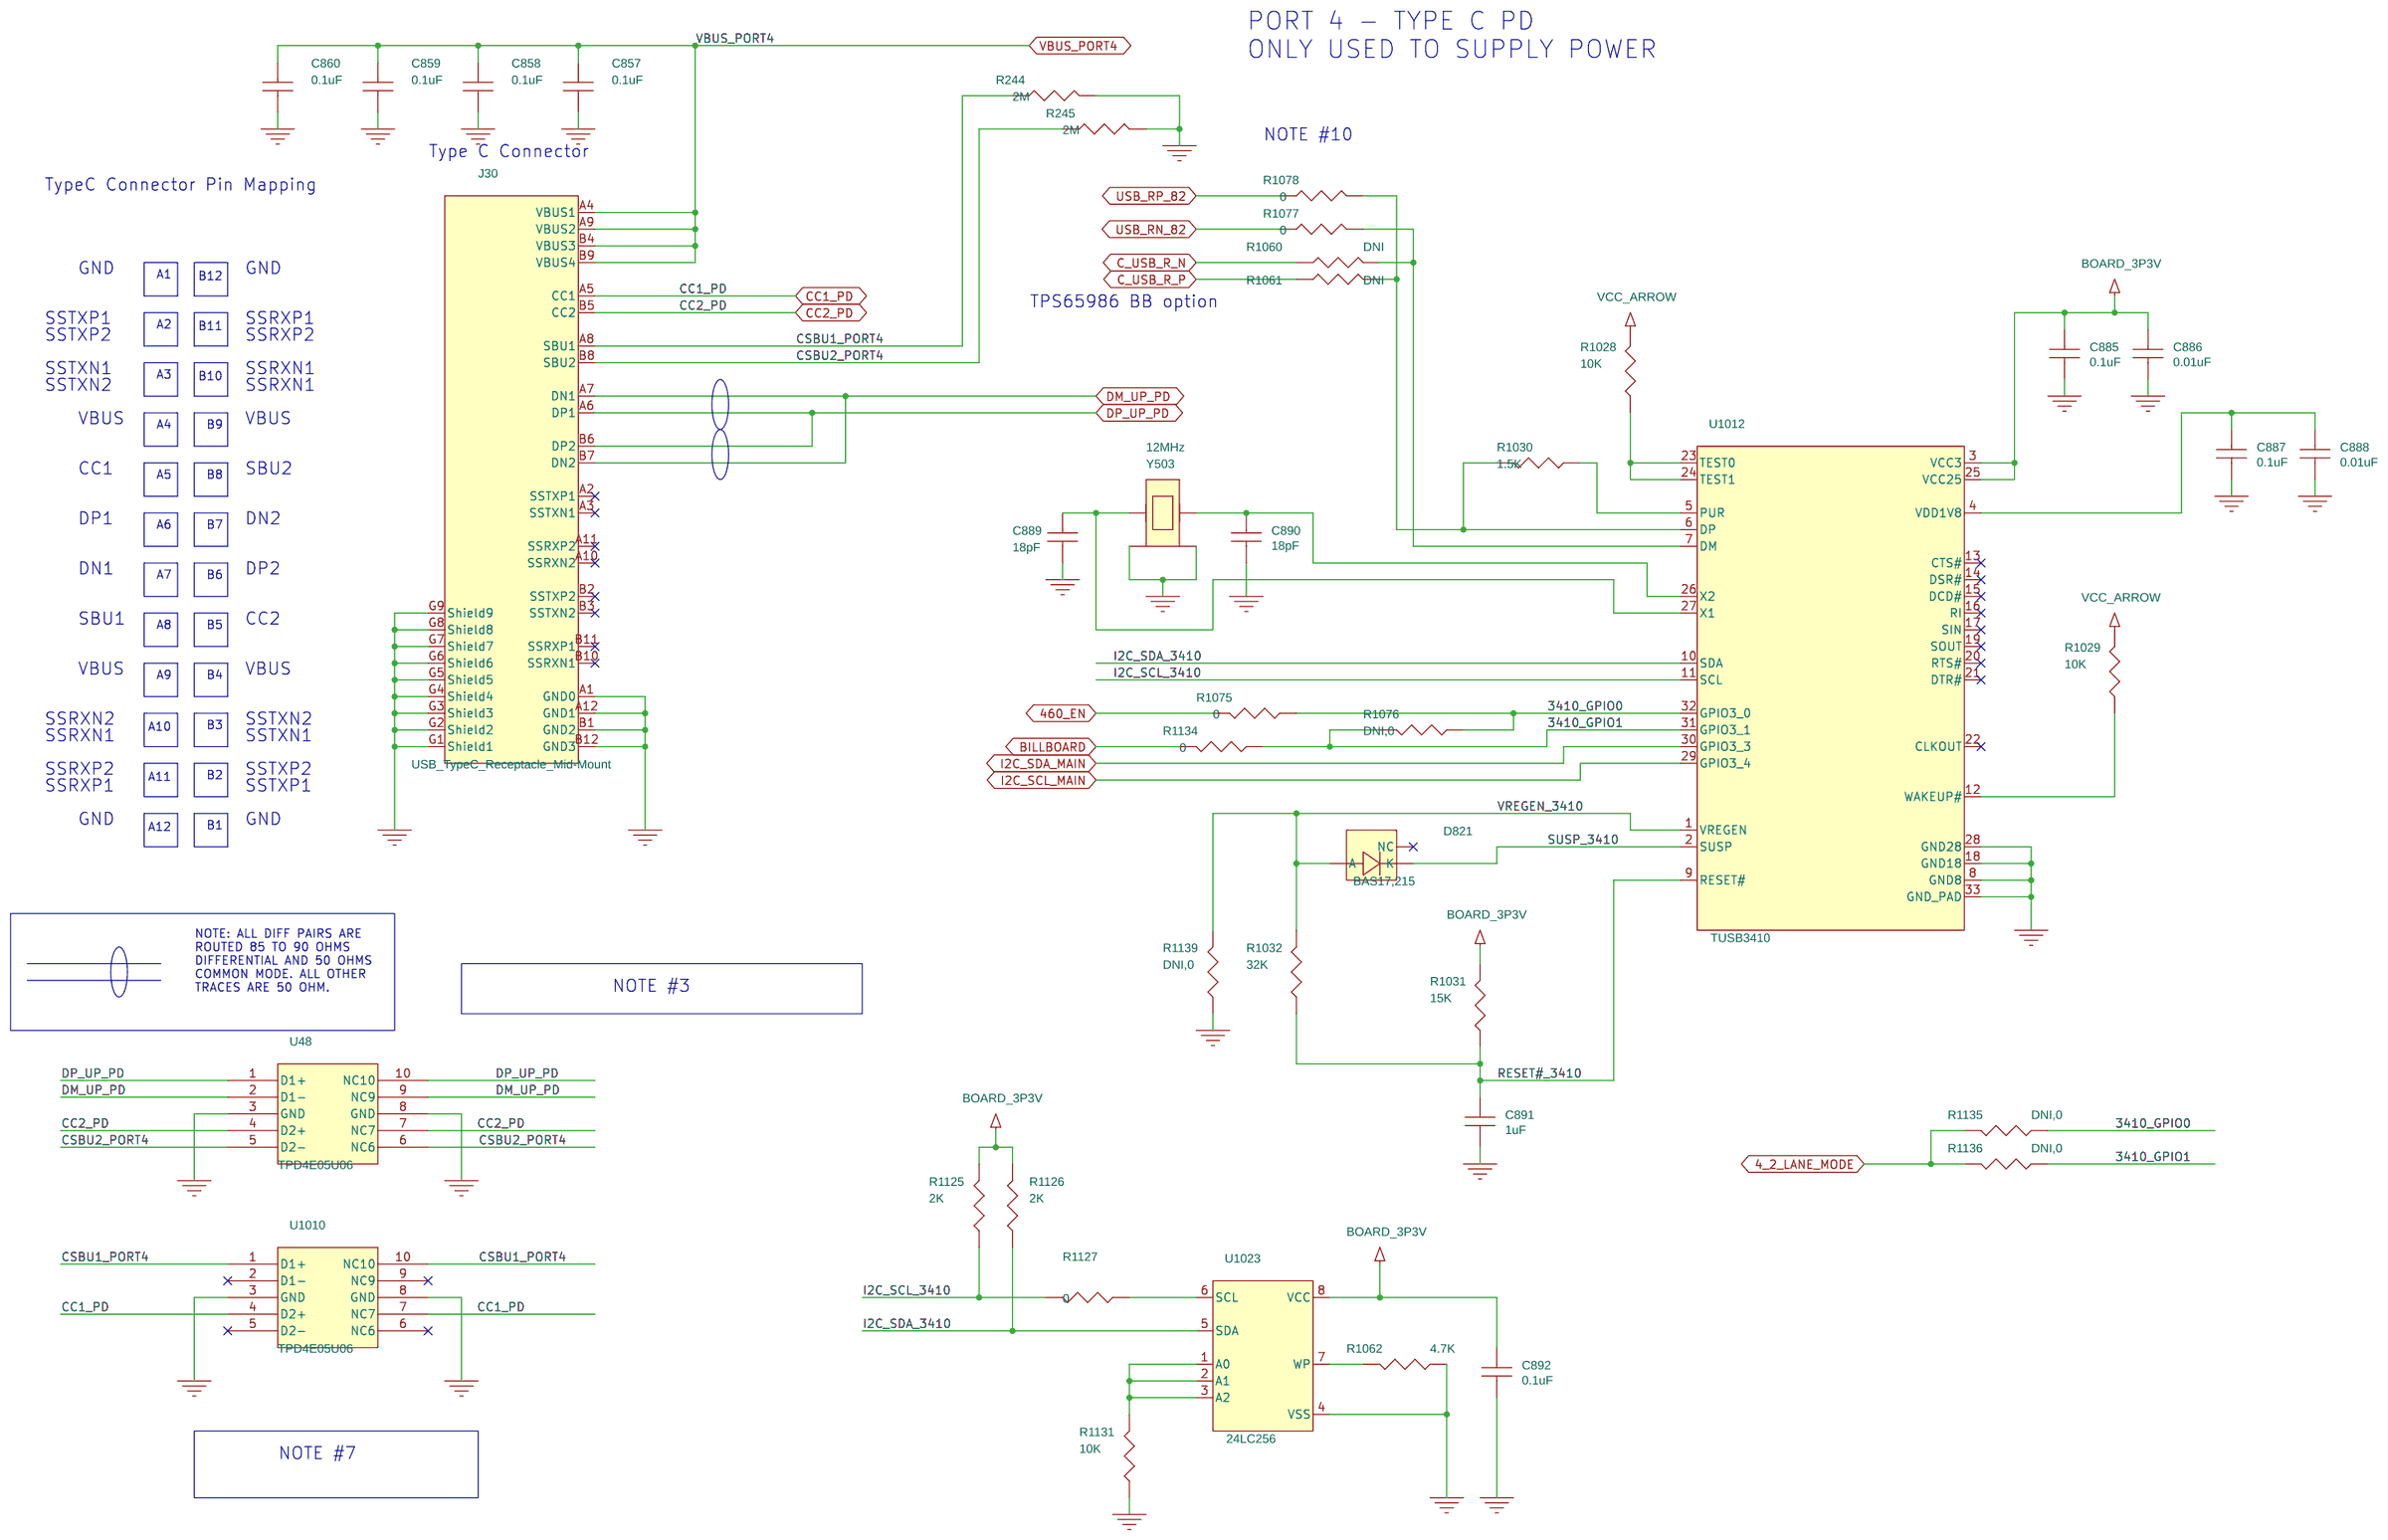
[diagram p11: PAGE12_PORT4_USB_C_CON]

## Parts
sheet PAGE02_POWER
C288  10uF  [C0805]
C289  470pF  [0201RND]
C290  10pF  [0201RND]
C291  8.2nF  [0201RND]
C292  100nF  [C0402]
C293  22uF  [C0603]
C294  1uF  [C0603]
C295  0.1uF  [0201RND]
C297  22uF  [C0603]
C298  1nF  [C0402]
C299  100nF  [C0402]
C300  100nF  [C0402]
C301  10uF  [C0805]
C302  22uF  [C0603]
C303  22uF  [C0603]
C304  22uF  [C0603]
C305  22uF  [C0603]
C376  0.1uF  [0201RND]
C377  22uF  [C0603]
C378  22uF  [C0603]
C833  0.1uF  [0201RND]
C834  0.1uF  [0201RND]
C835  0.1uF  [0201RND]
C836  10uF  [C0805]
C837  10uF  [C0805]
C838  10uF  [C0805]
C839  0.1uF  [0201RND]
C916  22uF  [C0805]
C917  22uF  [C0805]
C918  100uF, 16V  [TANT_7343-31]
D7  B540C-13-F  [SOD_128]
L24  3.3uH  [ind_sm_xal50]
L25  3.3uH  [ind_sm_xal50]
R173  49.9K  [0201RND]
R174  10.2K  [0201RND]
R175  3.24K  [0201RND]
R176  576K  [0201RND]
R177  100K  [0201RND]
R178  1K  [0201RND]
R179  86.6K  [0201RND]
R180  178K  [0201RND]
R181  69.8K  [R0402]
R182  10K  [R0402]
R183  1.91K  [R0402]
R184  100K  [0201RND]
U1  TPS54332  [DDA0008EA_213x300]
U2  TPS53318  [DQP_PSON_22]
sheet PAGE03_POWER2
C306  12pF  [0201RND]
C307  56pF  [0201RND]
C308  8.2nF  [0201RND]
C309  10uF  [C0805]
C310  0.1uF  [C0402]
C311  100nF  [C0402]
C312  22uF  [C0603]
C379  1uF  [C0402]
C380  0.1uF  [C0402]
C840  0.1uF  [C0402]
C841  22uF  [C0603]
C842  22uF  [C0603]
C843  22uF  [C0603]
C844  0.1uF  [C0402]
C845  0.1uF  [C0402]
D5  CD-0603T-24C  [C0805]
D8  B540C-13-F  [SOD_128]
D814  B540C-13-F  [SOD_128]
D822  GREEN LED  [LED_0603]
D823  BLUE LED  [LED_0603]
D831  B540C-13-F  [SOD_128]
J31  6140046600_DC_PWR_JACK  [Jack_THRT_JPD1135]
L26  2.2uH  [ind_sm_xal40]
MH1  MFG_125_PTH  [MFG_125_PTH]
MH2  MFG_125_PTH  [MFG_125_PTH]
MH3  MFG_125_PTH  [MFG_125_PTH]
MH4  MFG_125_PTH  [MFG_125_PTH]
Q9  2N7002K  [SOT_23_321]
Q23  DTC114EUAT106  [SOT_323-312]
Q25  DTC114EUAT106  [SOT_323-312]
R185  107K  [0201RND]
R186  20.5K  [0201RND]
R187  10.2K  [0201RND]
R264  100K  [R0402]
R265  10K  [R0402]
R936  DNI  [0201RND]
R937  DNI  [0201RND]
R1005  560  [R0402]
R1006  560  [R0402]
R1007  560  [R0402]
R1036  0  [R0402]
U3  TPS54331  [DDA0008EA_213x300]
U5  TLV3012  [DCK_PDSO_6]
sheet PAGE05_UPSTREAM_TPS65986
C322  1uF  [0201RND]
C323  10uF  [C0402]
C327  2.2uF  [C0402]
C328  10uF  [C0402]
C329  2.2uF  [C0402]
C330  22uF  [C0603]
C331  22uF  [C0603]
C332  10uF  [C0805]
C333  10uF  [C0805]
C381  1uF  [C0402]
C397  220pF  [0201RND]
C398  220pF  [0201RND]
C399  0.22uF  [0201RND]
C854  10uF  [C0805]
C855  0.1uF  [0201RND]
C856  0.01uF  [0201RND]
D12  NSR20F30NXT5G  [DIODE_DSN2]
D820  GREEN LED  [LED_0603]
FB13  23 @ 100MHZ,4A  [FB_0603]
Q24  DTC114EUAT106  [SOT_323-312]
R201  15K  [R0402]
R202  0  [0201RND]
R839  0  [0201RND]
R840  0  [0201RND]
R841  0  [0201RND]
R842  0  [0201RND]
R843  3.3K  [0201RND]
R844  3.3K  [0201RND]
R845  3.3K  [0201RND]
R846  3.3K  [0201RND]
R847  10K  [0201RND]
R848  10K  [0201RND]
R849  10K  [0201RND]
R853  100K  [R0402]
R854  1K  [R0402]
R855  DNI  [0201RND]
R858  0  [0201RND]
R942  3.3K  [0201RND]
R943  3.3K  [0201RND]
R946  DNI  [0201RND]
R947  DNI  [0201RND]
R1027  560  [R0402]
R1042  DNI,0  [0201RND]
R1043  DNI,0  [0201RND]
R1044  0  [0201RND]
R1045  0  [0201RND]
R1117  0  [0201RND]
R1118  0  [0201RND]
R1119  0  [0201RND]
R1120  0  [0201RND]
R1121  0  [0201RND]
R1122  0  [0201RND]
SW2  KMT211NGHF  [SW_SMVT_KTM2]
U52  TPS65986  [ZQZ_BGA_96]  (sections A,B)
U1007  W25Q80DVZP  [WSON_8_5x6mm_1p27mm]
sheet PAGE06_TUSB8041
C9  18pF  [C0402]
C10  18pF  [C0402]
C13  4.7uF  [C0402]
C78  0.01uF  [C0402]
C79  0.01uF  [C0402]
C80  0.1uF  [C0402]
C81  0.1uF  [C0402]
C82  0.01uF  [C0402]
C83  0.1uF  [C0402]
C84  10uF  [C0402]
C85  0.01uF  [C0402]
C86  0.01uF  [C0402]
C87  0.01uF  [C0402]
C88  0.1uF  [C0402]
C89  0.1uF  [C0402]
C90  10uF  [C0402]
C895  0.1uF  [C0402]
Q26  DTC114EUAT106  [SOT_323-312]
R2  2K  [R0402]
R17  DNI,1M  [R0402]
R20  9.53K, 1%  [R0402]
R32  28.7K  [R0402]
R35  2K  [R0402]
R39  10K  [R0402]
R40  10K  [R0402]
R45  10K  [R0402]
R46  DNI,10K  [R0402]
R62  DNI,0  [R0402]
R157  10K  [R0402]
R218  DNI,0  [R0402]
R219  10K  [R0402]
R266  10K  [R0402]
R275  10K  [R0402]
R1047  DNI,0  [R0402]
R1049  DNI,0  [R0402]
R1050  DNI,0  [R0402]
R1051  DNI,0  [R0402]
R1052  DNI,0  [R0402]
R1053  DNI,0  [R0402]
R1085  1K  [R0402]
R1086  1K  [R0402]
R1088  1K  [R0402]
R1108  DNI,0  [R0402]
R1115  DNI  [0201RND]
R1116  DNI  [0201RND]
SW3  KMT211NGHF  [SW_SMVT_KTM2]
U24  TUSB8041  [QFN_64_354SQ_20]  (sections -1,-2)
U33  TPS3831K33  [DQN]
U1020  AT24C04  [UDFN_8_2X3_0p5mm]
Y2  24MHz  [XTAL_4_SM_2x2p5mm]
sheet PAGE07_PORT1_USB3
C62  0.1uF  [0201RND]
C63  0.1uF  [C0402]
C72  0.1uF  [0201RND]
C321  10uF  [C0603]
C374  22uF  [C0603]
C862  47uF  [cap_sm_fk_d]
D824  GREEN LED  [LED_0603]
FB10  220 @ 100MHZ,2A  [FB_0603]
J10  USB3_TYPEA_CONNECTOR  [CON_THRT_USB3A_FCI]
L28  2.2uH  [IND_DRA74]
Q27  DTC114EUAT106  [SOT_323-312]
R195  560  [R0402]
R196  20.5K  [R0402]
R197  10K  [R0402]
R268  0  [R0402]
R269  0  [R0402]
R1008  0  [R0402]
R1054  DNI,0  [R0402]
R1055  DNI,0  [R0402]
R1109  0  [R0402]
U14  TPD6E05U06  [RVZ_PUSON_14]
U34  TPS2500  [DRC_S_PVSON_N10B]
sheet PAGE08_PORT2_USBC
C340  0.1uF  [0201RND]
C341  0.1uF  [0201RND]
C342  0.1uF  [0201RND]
C343  0.1uF  [0201RND]
C344  0.1uF  [C0402]
C372  1uF  [C0402]
C373  0.1uF  [C0402]
C382  DNI,10uF  [C0603]
C393  47nf  [C0402]
C863  DNI,0.1uF  [C0402]
C864  DNI,0.1uF  [C0402]
C865  0.1uF  [C0402]
C882  10uF  [C0603]
D825  GREEN LED  [LED_0603]
D826  RED LED  [LED_0603]
FB605  23 @ 100MHZ,4A  [FB_0603]
J29  USB_TypeC_Receptacle_Mid-Mount  [USB_typeC_20-0000016-01]
Q13  2N7002K  [SOT_23_321]
Q28  DTC114EUAT106  [SOT_323-312]
Q29  DTC114EUAT106  [SOT_323-312]
R230  2M  [0201RND]
R231  2M  [0201RND]
R262  54.9K  [0201RND]
R263  0  [0201RND]
R270  DNI,10K  [0201RND]
R271  10K  [0201RND]
R1009  560  [R0402]
R1010  560  [R0402]
R1011  0  [R0402]
R1012  10K  [R0402]
R1034  0  [0201RND]
R1035  DNI  [0201RND]
R1112  0  [0201RND]
U38  TPD4E05U06  [DQA]
U39  TPD4E05U06  [DQA]
U40  TPD4E05U06  [DQA]
U41  TPD4E05U06  [DQA]
U51  TPS25910  [RSA0016BA_270x270]
sheet PAGE09_PORT2_USBC_2
C366  10uF  [C0402]
C367  0.1uF  [C0402]
C369  0.1uF  [C0402]
C371  10uF  [C0603]
R246  0  [0201RND]
R248  10K  [0201RND]
R250  DNI,10K  [0201RND]
R253  200K  [0201RND]
R254  200K  [0201RND]
R255  200K  [0201RND]
R257  10K  [0201RND]
R258  200K  [0201RND]
R259  0  [0201RND]
R260  DNI  [0201RND]
R272  909K  [R0402]
R282  DNI  [0201RND]
R283  0  [0201RND]
R935  10K  [0201RND]
U49  HD3SS3212  [RKS_R-PVQFN-N20]
U53  TUSB321  [RWB_X2QFN_12]
sheet PAGE10_PORT3_USB_AUDIO
C345  1uF  [C0402]
C383  1uF  [C0402]
C384  18pF  [C0402]
C385  18pF  [C0402]
C386  1uF  [C0402]
C387  1uF  [C0402]
C388  10uF  [C0805]
C389  0.022uF  [C0402]
C390  0.022uF  [C0402]
C391  100uF  [cap_rad_sm_4x5p4mm]
C392  100uF  [cap_rad_sm_4x5p4mm]
J16  CONN_AUD_3P_J_H  [Jack_SMRT_SJ-3523]
R273  1M  [R0402]
R274  1.5K  [R0402]
R276  16  [R0402]
R277  16  [R0402]
R278  3.3K  [R0402]
R279  3.3K  [R0402]
R280  DNI,3.3K  [R0402]
R281  DNI,3.3K  [R0402]
R950  DNI  [R0402]
R951  DNI  [R0402]
R952  DNI  [R0402]
R953  DNI  [R0402]
R954  DNI  [R0402]
R955  DNI  [R0402]
R956  DNI  [R0402]
R957  DNI  [R0402]
R958  DNI  [R0402]
R959  DNI  [R0402]
R960  DNI  [R0402]
R961  DNI  [R0402]
R962  DNI  [R0402]
R963  DNI  [R0402]
R964  DNI  [R0402]
R965  DNI  [R0402]
R966  DNI  [R0402]
R967  DNI  [R0402]
R1110  1.5K  [R0402]
R1140  0  [R0402]
R1141  0  [R0402]
R1142  DNI,0  [R0402]
R1143  DNI,0  [R0402]
U42  PCM2707C  [PJT0032AA]
Y3  12MHz  [XTAL_4_SM_2x2p5mm]
sheet PAGE11_PORT4_USB_C_CHARGING
C346  22uF  [C0603]
C347  22uF  [C0603]
C348  10uF  [C0805]
C349  10uF  [C0805]
C350  1uF  [C0402]
C353  1uF  [0201RND]
C354  10uF  [C0402]
C355  2.2uF  [C0402]
C356  10uF  [C0402]
C357  2.2uF  [C0402]
C375  1uF  [C0402]
C394  220pF  [0201RND]
C395  220pF  [0201RND]
C396  0.22uF  [0201RND]
C883  0.01uF  [0201RND]
D13  NSR20F30NXT5G  [DIODE_DSN2]
FB14  120 @ 100MHZ,5A  [FB_0805]
R233  0.005  [R0805]
R236  15K  [R0402]
R237  DNI,0  [0201RND]
R288  10K  [0201RND]
R859  DNI,0  [0201RND]
R862  DNI,0  [R0805]
R877  10K  [0201RND]
R878  10K  [0201RND]
R970  100K  [R0402]
R971  1K  [R0402]
R1056  DNI  [0201RND]
R1057  DNI  [0201RND]
R1058  0  [0201RND]
R1059  0  [0201RND]
R1113  0  [0201RND]
R1114  0  [0201RND]
R1123  0  [0201RND]
R1124  0  [0201RND]
R1144  0  [R0805]
SW503  KMT211NGHF  [SW_SMVT_KTM2]
U43  TPS65982  [ZQZ_BGA_96]  (sections A,B)
U44  CSD87501L  [YJG0010AA]
sheet PAGE12_PORT4_USB_C_CON
C857  0.1uF  [C0402]
C858  0.1uF  [C0402]
C859  0.1uF  [C0402]
C860  0.1uF  [C0402]
C885  0.1uF  [C0402]
C886  0.01uF  [C0402]
C887  0.1uF  [C0402]
C888  0.01uF  [C0402]
C889  18pF  [C0402]
C890  18pF  [C0402]
C891  1uF  [C0402]
C892  0.1uF  [C0402]
D821  BAS17,215  [SOT_23_321]
J30  USB_TypeC_Receptacle_Mid-Mount  [USB_typeC_20-0000016-01]
R244  2M  [R0402]
R245  2M  [R0402]
R1028  10K  [R0402]
R1029  10K  [R0402]
R1030  1.5K  [R0402]
R1031  15K  [R0402]
R1032  32K  [R0402]
R1060  DNI  [0201RND]
R1061  DNI  [0201RND]
R1062  4.7K  [R0402]
R1075  0  [R0402]
R1076  DNI,0  [R0402]
R1077  0  [0201RND]
R1078  0  [0201RND]
R1125  2K  [R0402]
R1126  2K  [R0402]
R1127  0  [R0402]
R1131  10K  [R0402]
R1134  0  [R0402]
R1135  DNI,0  [R0402]
R1136  DNI,0  [R0402]
R1139  DNI,0  [R0402]
U48  TPD4E05U06  [DQA]
U1010  TPD4E05U06  [DQA]
U1012  TUSB3410  [RHB0032BA_345X345]
U1023  24LC256  [SOIC_8_197x157_50]
Y503  12MHz  [XTAL_4_SM_2x2p5mm]

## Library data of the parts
C9 C10 C13 C62 C63 C72 C288-C295 C297-C312 C321-C323 C327-C333 C340-C343 C346-C350 C353-C357 C366 C367 C369 C372-C381 C393-C399 C833-C845 C854-C856 C882 C883 C885-C892 C895 C916 C917 = CAP_NP: 6.3V Capacitor
C918 = CAPACITOR_POL_SM: MANUFACTURER: Kemet; MANUFACTURER'S PART NUMBER: T491D107K016AT; Manufacturer Part Number: T491D107K016AT; Part Number: T491D107K016AT
D7 D8 D814 D831 = DIODE_SCHOTTKY_0: Manufacturer: NXP Semi; Manufacturer's Part Number: PMEG3050EP,115
L24 L25 = INDUCTOR: Manufacturer: Coilcraft; Manufacturer's Part Number: XAL5030-332MEB
R173-R187 R195-R197 R264 R265 R268 R269 R936 R937 R1005-R1008 R1028-R1032 R1036 R1054 R1055 R1062 R1075 R1076 R1109 R1125-R1127 R1131 R1134-R1136 R1139 = R: Resistor; Tolerance: 5%
U1 = TPS54332_0: MANUFACTURER: TEXAS INSTRUMENTS; MANUFACTURER'S PART NUMBER: TPS54332DDAR
U2 = TPS53318: Manufacturer: Texas Instruments; Manufacturer's Part Number: TPS53318DQPR
D5 = SMBJ20CA_0: MANUFACTURER: BOURNS
D822 = LED_0: MANUFACTURER: LITE-ON; MANUFACTURER'S PART NUMBER: LTST-C191GKT; TI_SILKTEXT: P1_5V
D823 = LED_0: MANUFACTURER: VISHAY; MANUFACTURER'S PART NUMBER: TLMB1100-GS08; TI_SILKTEXT: 20V
J31 = FOXCONN_DC_JACK: DEVICE_NAME: DC_PWR_JACK; MANUFACTURER: FOXCONN; MANUFACTURER'S PART NUMBER: JPD1135-509-7F; TI_SILKTEXT: 20VIN
L26 = INDUCTOR: Manufacturer: Coilcraft; Manufacturer's Part Number: XAL4020-222MEB
MH1-MH4 = MTG_125
Q9 Q13 = 2N7002_1: Manufacturer: VISHAY; Manufacturer's Part Number: 2N7002K-T1-E3
Q23-Q29 = DTC114EUAT106: MANUFACTURER: Rohm Semi; Manufacturer Part Number: DTC114EAUT106
U3 = TPS54331: Manufacturer: Texas Instruments; Manufacturer's Part Number: TPS54331DDAR
U5 = TLV3012: MANUFACTURER: TEXAS INSTRUMENTS; MANUFACTURER'S PART NUMBER: TLV3012AIDCKR
D12 D13 = DIODE_SCHOTTKY_0: Manufacturer: ON SEMI
D820 = LED_0: MANUFACTURER: LITE-ON; MANUFACTURER'S PART NUMBER: LTST-C191GKT; TI_SILKTEXT: DPMODE
FB13 FB605 = FERRITE_BEAD_v2: Ferrite Bead; Digi-Key Part Number: 490-3992-1-ND; Manufacturer: Taiyo Yuden; Manufacturer's Part Number: FBMJ1608HM230NT
R2 R20 R32 R35 R39 R40 R45 R46 R201 R202 R218 R219 R230 R231 R236 R237 R244-R246 R250 R262 R263 R270 R271 R273 R274 R276-R281 R288 R839-R849 R853-R855 R858 R859 R862 R877 R878 R942 R943 R946 R947 R950-R967 R970 R971 R1009-R1012 R1027 R1034 R1035 R1042-R1045 R1047 R1049-R1053 R1056-R1061 R1077 R1078 R1085 R1086 R1088 R1110 R1112-R1114 R1117-R1124 R1140-R1144 = R
SW2 = KMT211GHF: MANUFACTURER: C&K; MANUFACTURER'S PART NUMBER: KMT211NGHFLFS; TI_SILKTEXT: 86RST
U52 = TPS65986: MANUFACTURER: TEXAS INSTRUMENTS
U1007 = W25Q80DV: MANUFACTURER: WINBOND ELECTRONICS
C78-C90 = CAP_NP
R17 R62 R1108 = R: Resistor
R157 R266 R275 R1115 R1116 = RES: Resistor; $SEC: 1; CDS_LIB: resistor; DRAWING: @LIGHTNING_BOLT_NB_LIB.NOTE_BOOK(SCH_1):PAGE1; PHYS_PAGE: 1; ROT: 4; TOLERANCE: 5%; VER: 1; WATTAGE: 1/16W; XY: (-3000,6550)
SW3 = KMT211GHF: MANUFACTURER: C&K; MANUFACTURER'S PART NUMBER: KMT211NGHFLFS; TI_SILKTEXT: HUBRST
U24 = TUSB8041: Color: Default; Location X-Coordinate: 0; Location Y-Coordinate: 0; MANUFACTURER: TEXAS INSTRUMENTS; MANUFACTURER'S PART NUMBER: TUSB8041RGC; Package Type: Heterogeneous; Power Pins Visible: False; Primitive: DEFAULT; SPLIT_INST: TRUE; SWAP_INFO: (S1+S2)
U33 = TPS3831K33: MANUFACTURER: TEXAS INSTRUMENTS; MANUFACTURER'S PART NUMBER: TPS3831K50DQNR
U1020 = AT24C04_0: Manufacturer: Atmel; Manufacturer's Part Number: AT24C04D-MAHM
Y2 = CRYSTAL_4_PIN: MANUFACTURER: TXC CORP; MANUFACTURER'S PART NUMBER: 8Z-24.000MAAJ-T
C862 = CAP: MANUFACTURER: PANASONIC; MANUFACTURER'S PART NUMBER: EEE-FT1C470AR
D824 = LED_0: MANUFACTURER: LITE-ON; MANUFACTURER'S PART NUMBER: LTST-C191GKT; TI_SILKTEXT: P1
FB10 = FERRITE_BEAD_v2: Ferrite Bead; Digi-Key Part Number: 490-3992-1-ND; Manufacturer: MuRata; Manufacturer's Part Number: BLM18EG221SN1D
J10 = USB3_TYPEA_CONNECTER_2: USB3 Type A Connector; Manufacturer: FCI; Manufacturer's Part Number: 10117835-002LF; TI_Silktext: DFP1
L28 = INDUCTOR: Manufacturer: EATON BUSSMANN; Manufacturer's Part Number: DR74-2R2-R
U14 = TPD6E05U06: MANUFACTURER: TEXAS INSTRUMENTS; MANUFACTURER'S PART NUMBER: TPD6E05U06RVZR
U34 = TPS2500: MANUFACTURER: TEXAS INSTRUMENTS; MANUFACTURER'S PART NUMBER: TPS2500DRCT
C344 C345 C382-C387 C389 C390 C857-C860 C863-C865 = CAP_NP: 25V Capacitor
D825 = LED_0: MANUFACTURER: LITE-ON; MANUFACTURER'S PART NUMBER: LTST-C191GKT; TI_SILKTEXT: P2PWR
D826 = LED_0: MANUFACTURER: LITE-ON; MANUFACTURER'S PART NUMBER: LTST-C190EKT; TI_SILKTEXT: P2PWR
J29 = USBTypeC_Receptacle_TOPMount_0: MANUFACTURER: LINTES; MANUFACTURER'S PART NUMBER: AUSB0129; TI_SILKTEXT: DFP2
U38-U41 U48 U1010 = TPD4E05U06: MANUFACTURER'S PART NUMBER: TPD4E05U06DQAR
U51 = TPS25910: MANUFACTURER: TEXAS INSTRUMENTS; MANUFACTURER'S PART NUMBER: TPS25910RSAR
C371 = CAP_v2: 6.3V Capacitor; $SEC: 1; CDS_LIB: capacitor; PHYS_PAGE: 1; ROT: 0; TOLERANCE: 10%; VER: 1; VOLTAGE: 6.3V; XY: (-9500,3550)
R248 R253-R255 R257 R258 R935 = RES: Resistor; $SEC: 1; ATIPartNo: 3150010400G; CDS_LIB: resistor; DRAWING: @LIGHTNING_BOLT_NB_LIB.NOTE_BOOK(SCH_1):PAGE1; PHYS_PAGE: 1; ROT: 4; TOLERANCE: 5%; VER: 1; WATTAGE: 1/16W; XY: (-9550,4950)
R259 R260 R272 R282 R283 = R_2: Resistor; Manuf: TBD; Manuf PN: TBD; Tolerance: 5%
U49 = HD3SS3212: MANUFACTURER: TEXAS INSTRUMENTS; MANUFACTURER'S PART NUMBER: HD3SS3212IRKSR
U53 = TUSB321: MANUFACTURER: TEXAS INSTRUMENTS; MANUFACTURER'S PART NUMBER: TUSB321RWBR
C388 = CAP_POL: MANUFACTURER: MURATA; MANUFACTURER'S PART NUMBER: GRM21BR71A106KE51K
C391 C392 = CAP_POL: MANUFACTURER: PANASONIC; MANUFACTURER'S PART NUMBER: EEE-1AA101WR
J16 = CONN_AUD_3P_J_H: MANUFACTURER: CUI; MANUFACTURER'S PART NUMBER: SJ-3523-SMT; TI_SILKTEXT: AUDIO
U42 = PCM2707C: MANUFACTURER: TEXAS INSTRUMENTS; MANUFACTURER'S PART NUMBER: PCM2707CPJTR
Y3 Y503 = CRYSTAL_4_PIN: MANUFACTURER: TXC CORP; MANUFACTURER'S PART NUMBER: 8Z-12.000MAAJ-T
FB14 = FERRITE_BEAD_v2: Ferrite Bead; Digi-Key Part Number: 490-3992-1-ND; Manufacturer: Samsung; Manufacturer's Part Number: CIS21J121NE
R233 = R: MANUFACTURER: Bourns; MANUFACTURER'S PART NUMBER: CRF0805-FX-R005ELF; Manufacturer Part Number: Bourns
SW503 = KMT211GHF: MANUFACTURER: C&K; MANUFACTURER'S PART NUMBER: KMT211NGHFLFS; TI_SILKTEXT: 82RST
U43 = TPS65982: MANUFACTURER: TEXAS INSTRUMENTS; MANUFACTURER'S PART NUMBER: TPS65982ABZQZR
U44 = CDS87501L: MANUFACTURER: TEXAS INSTRUMENTS
D821 = DIODE_3: MANUFACTURER: NXP
J30 = USBTypeC_Receptacle_TOPMount_0: MANUFACTURER: LINTES; MANUFACTURER'S PART NUMBER: AUSB0129; TI_SILKTEXT: DFP4
U1012 = TUSB3410_0: MANUFACTURER: TEXAS INSTRUMENTS; MANUFACTURER'S PART NUMBER: TUSB3410IRHB
U1023 = 24LC256: MANUFACTURER: MICROCHIP TECH; MANUFACTURER'S PART NUMBER: 24LC256T-I/SN

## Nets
5V_AUX: C374.1 Q26.3(C) R218.1 R1109.1 U34.10(AUX) U42.3(HOST) ; also on sheet 18
GND: C9.2 C10.2 C13.2 C63.2 C78.2 C79.2 C80.2 C81.2 C82.2 C83.2 C84.2 C85.2 C86.2 C87.2 C88.2 C89.2 C90.2 C288.2 C289.2 C290.2 C291.2 C293.2 C294.2 C295.2 C297.2 C301.2 C302.2 C303.2 C304.2 C305.2 C306.2 C307.2 C308.2 C309.2 C310.2 C312.2 C321.2 C322.1 C323.1 C327.1 C328.1 C329.1 C330.1 C331.1 C332.1 C333.1 C344.2 C345.2 C346.1 C347.1 C348.1 C349.1 C350.1 C353.1 C354.1 C355.1 C356.1 C357.1 C366.2 C367.2 C369.2 C371.2(B) C372.2 C373.2 C374.2 C375.1 C376.2 C377.2 C378.2 C379.2 C380.2 C381.1 C382.2 C383.2 C384.2 C385.2 C386.2 C387.2 C388.2 C393.2 C394.1 C395.1 C396.1 C397.1 C398.1 C399.1 C833.2 C834.2 C835.2 C836.2 C837.2 C838.2 C839.2 C840.2 C841.2 C842.2 C843.2 C844.2 C845.2 C854.1 C855.1 C856.1 C857.2 C858.2 C859.2 C860.2 C862.2 C863.2 C864.2 C865.2 C882.2 C883.1 C885.2 C886.2 C887.2 C888.2 C889.2 C890.2 C891.2 C892.2 C895.2 C916.2 C917.2 C918.2 D5.1 D7.2(ANODE) D8.2(ANODE) D12.2(ANODE) D13.2(ANODE) J10.4(GND) J10.7(GND) J10.10(SHLD) J10.11(SHLD1) J16.3 J29.A1(GND0) J29.A12(GND1) J29.B1(GND2) J29.B12(GND3) J29.G1(Shield1) J29.G2(Shield2) J29.G3(Shield3) J29.G4(Shield4) J29.G5(Shield5) J29.G6(Shield6) J29.G7(Shield7) J29.G8(Shield8) J29.G9(Shield9) J30.A1(GND0) J30.A12(GND1) J30.B1(GND2) J30.B12(GND3) J30.G1(Shield1) J30.G2(Shield2) J30.G3(Shield3) J30.G4(Shield4) J30.G5(Shield5) J30.G6(Shield6) J30.G7(Shield7) J30.G8(Shield8) J30.G9(Shield9) J31.4(GND#4) J31.5(GND#5) J31.6(SH1) J31.7(SH2) J31.8(SH3) J31.9(SH4) MH1.1 MH2.1 MH3.1 MH4.1 Q9.2(SOURCE) Q13.2(SOURCE) Q23.1(E) Q24.1(E) Q25.1(E) Q27.1(E) Q28.1(E) Q29.1(E) R20.2 R39.2 R45.2 R46.2 R175.2 R177.2 R179.2 R180.2 R182.2 R186.2 R201.1 R202.1 R230.2 R231.2 R236.1 R237.1 R244.2 R245.2 R250.2 R263.1 R265.2 R269.2 R276.1 R277.1 R278.1 R279.1 R280.1 R281.1 R288.1 R853.1 R855.1 R937.2 R959.1 R960.1 R961.1 R962.1 R963.1 R964.1 R965.1 R966.1 R967.1 R970.1 R1052.2 R1053.2 R1062.2 R1085.2 R1086.2 R1088.2 R1131.2 R1139.2 R1140.1 R1141.1 SW3.3 SW3.4 U1.7(GND) U1.9(GND_PAD) U2.5(ROVP) U2.23(GND) U3.7(GND) U3.9(GND_PAD) U5.2(V-) U14.5(GND5) U14.10(GND10) U24.65(PAD) U33.3(GND) U33.5(TPAD) U34.2(PGND) U34.5(GND) U34.11(GND_PAD) U38.3(GND) U38.8(GND) U39.3(GND) U39.8(GND) U40.3(GND) U40.8(GND) U41.3(GND) U41.8(GND) U42.1(PGND) U42.20(DGND) U42.25(ZGND+) U42.26(AGNDL) U42.31(AGNDR) U43.A1(GND1) U43.B8(GND2) U43.D8(GND3) U43.E5(GND4) U43.E6(GND5) U43.E7(GND6) U43.E8(GND7) U43.F5(GND8) U43.F6(GND9) U43.F7(GND10) U43.F8(GND11) U43.G5(GND12) U43.G6(GND13) U43.G7(GND14) U43.G8(GND15) U43.H4(GND16) U43.H5(GND17) U43.H8(GND18) U43.L1(GND19) U48.3(GND) U48.8(GND) U49.5(GND5) U49.11(GND11) U49.20(GND20) U49.21(PAD) U51.5(GND5) U51.6(GND6) U51.8(GND4) U51.9(GND3) U51.13(GND2) U51.14(GND1) U51.17(GND_PAD) U52.A1(GND1) U52.A5(GND21) U52.B5(GND20) U52.B8(GND2) U52.D8(GND3) U52.E5(GND4) U52.E6(GND5) U52.E7(GND6) U52.E8(GND7) U52.F5(GND8) U52.F6(GND9) U52.F7(GND10) U52.F8(GND11) U52.G5(GND12) U52.G6(GND13) U52.G7(GND14) U52.G8(GND15) U52.H4(GND16) U52.H5(GND17) U52.H8(GND18) U52.L1(GND19) U52.L4(GND22) U53.10(GND) U1007.4(GND) U1007.9(GND_PAD) U1010.3(GND) U1010.8(GND) U1012.8(GND8) U1012.18(GND18) U1012.28(GND28) U1012.33(GND_PAD) U1020.4(GND) U1020.9(PAD) U1023.4(VSS) Y2.2 Y2.4 Y3.2 Y3.4 Y503.2 Y503.4 ; also on sheet 13 14 15 16 17 18 19 20
VBUS_P1_FB: C63.1 FB10.1 J10.1(VBUS)
VBUS_PORT1: C862.1 FB10.2 R195.1 R1005.1 R1006.1 R1009.2 R1027.2 U34.9(USB) ; also on sheet 16 18
VBUS_PORT2: C382.1 FB605.2 R272.2 U51.10(OUT3) U51.11(OUT2) U51.12(OUT1)
VBUS_PORT4: C857.1 C858.1 C859.1 C860.1 D13.1(CATHODE) FB14.2 J30.A4(VBUS1) J30.A9(VBUS2) J30.B4(VBUS3) J30.B9(VBUS4)
VBUS_SENSE: C854.2 FB13.1 U52.A10(SENSEN) U52.B10(SENSEP) U52.H11(VBUS1) U52.J10(VBUS2) U52.J11(VBUS3) U52.K11(VBUS4)
VBUS_UPSTREAM: D12.1(CATHODE) FB13.2 ; also on sheet 20
4_2_LANE_MODE: R855.2 R1121.1 R1135.1 R1136.1 ; also on sheet 15
82_HRESET: C883.2 R970.2 SW503.1 SW503.2 U43.D6(HRESET)
321_FLT#: R255.2(B) U53.6(FLT#)
321_ID#: R253.1(A) R1034.2 U53.9(ID)
321_OUT1: R254.2(B) U53.7(OUT1)
321_OUT2: R258.2(B) U53.8(OUT2)
460_EN: R219.2 R1075.1 R1118.1 ; also on sheet 20
3212_ID#: R250.1 U49.2(OE#)
3410_GPIO0: R1075.2 R1076.2 R1135.2 U1012.32(GPIO3_0)
3410_GPIO1: R1076.1 R1134.2 R1136.2 U1012.31(GPIO3_1)
8041_EN: R1047.1 R1122.1
8041_USB_N: R1045.1 R1116.2(B) U24.25(USB_DM_DN4)
8041_USB_P: R1044.1 R1115.2(B) U24.24(USB_DP_DN4)
25910_GATE: C393.1 R270.1 U51.4(GATE)
AMSEL: R1117.1 ; also on sheet 15 20
AUTO_EN: R46.1 R1051.2 U24.45(AUTOEN/HS_SUSPD)
AUX_N: U52.J2(AUX_N) ; also on sheet 13 15
AUX_P: U52.J1(AUX_P) ; also on sheet 13 15
BILLBOARD: R1134.1 U52.L3(DEBUG3)
BOARD_1P2V: C78.1 C79.1 C80.1 C81.1 C82.1 C83.1 C84.1 C85.1 C312.1 C841.1 C842.1 C843.1 C844.1 C845.1 L26.2 R187.1 U24.5(VDD1) U24.8(VDD2) U24.13(VDD3) U24.21(VDD4) U24.28(VDD5) U24.31(VDD6) U24.51(VDD7) U24.57(VDD8) ; also on sheet 14 17
BOARD_3P3V: C86.1 C87.1 C88.1 C89.1 C90.1 C293.1 C321.1 C328.2 C345.1 C356.2 C366.1 C367.1 C377.1 C378.1 C383.1 C386.1 C387.1 C833.1 C885.1 C886.1 C892.1 C895.1 L24.2 L28.1 R2.1 R35.1 R40.1 R157.2(B) R174.1 R197.1 R248.1(A) R255.1(A) R266.2(B) R268.1 R271.2 R274.2 R275.2(B) R854.2 R950.2 R951.2 R952.2 R953.2 R954.2 R955.2 R956.2 R957.2 R958.2 R971.2 R1007.1 R1008.1 R1010.2 R1012.2 R1028.1 R1029.1 R1031.1 R1049.1 R1050.1 R1051.1 R1110.2 R1125.1 R1126.1 R1142.2 R1143.2 U24.16(VDD33_1) U24.34(VDD33_2) U24.52(VDD33_3) U24.63(VDD33_4) U33.4(VDD) U34.3(IN) U42.2(VCCP) U42.10(TEST) U42.21(VDD) U42.24(VBUS) U42.27(VCCL) U42.30(VCCR) U43.B1(VDDIO) U43.H1(VIN_3V3) U49.6(VCC6) U52.B1(VDDIO) U52.H1(VIN_3V3) U1012.3(VCC3) U1012.25(VCC25) U1020.8(VCC) U1023.8(VCC) ; also on sheet 13 14 15 16 17 18 19 20
BOARD_5V: C297.1 C300.2 C302.1 C303.1 C304.1 C305.1 C330.2 C331.2 C346.2 C347.2 C369.1 C371.1(A) C372.1 C373.1 C835.1 C882.1 C916.1 C917.1 C918.1 L25.2 R181.1 R253.2(B) R254.1(A) R257.1(A) R258.1(A) R270.2 R935.1(A) U43.A11(PP_5V0_1) U43.B11(PP_5V0_2) U43.C11(PP_5V0_3) U43.D11(PP_5V0_4) U43.H10(PP_CABLE) U51.1(IN1) U51.2(IN2) U51.3(IN3) U52.A11(PP_5V0_1) U52.B11(PP_5V0_2) U52.C11(PP_5V0_3) U52.D11(PP_5V0_4) U52.H10(PP_CABLE) U53.12(VDD) ; also on sheet 16
BOARD_20V: C288.1 C295.1 C301.1 C309.1 C310.1 C332.2 C333.2 C376.1 C834.1 C836.1 C837.1 C838.1 C839.1 C840.1 D5.2 D814.1(CATHODE) D831.1(CATHODE) R176.1 R264.1 R862.1 R936.1 R1144.1 U1.2(VIN) U2.12(VIN1) U2.13(VIN2) U2.14(VIN3) U2.15(VIN4) U2.16(VIN5) U2.17(VIN6) U2.19(VDD) U3.2(VIN) U52.A6(PP_HV3) U52.A7(PP_HV2) U52.A8(PP_HV1) U52.B7(PP_HV4)
BUSPOWERZ: R858.2 U52.F10(BUSPOWERZ)
BUSPOWERZ_82: R288.2 R859.2 U43.F10(BUSPOWERZ)
C_USB_R_N: R1060.1 R1116.1(A)
C_USB_R_P: R1061.1 R1115.1(A)
CC1_65986: C398.2 U52.K9(RPD_G1) U52.L9(C_CC1) ; also on sheet 20
CC1_PD: C395.2 J30.A5(CC1) U43.K9(RPD_G1) U43.L9(C_CC1) U1010.4(D2+) U1010.7(NC7)
CC1_PORT2: J29.A5(CC1) R260.2 R283.2 U39.1(D1+) U39.10(NC10)
CC1_R: R282.1 R283.1 U53.1(CC1)
CC2_65986: C397.2 U52.K10(RPD_G2) U52.L10(C_CC2) ; also on sheet 20
CC2_PD: C394.2 J30.B5(CC2) U43.K10(RPD_G2) U43.L10(C_CC2) U48.4(D2+) U48.7(NC7)
CC2_PORT2: J29.B5(CC2) R259.2 R282.2 U38.4(D2+) U38.7(NC7)
CC2_R: R259.1 R260.1 U53.2(CC2)
CSBU1_65986: U52.K8(C_SBU1) ; also on sheet 20
CSBU1_PORT2: J29.A8(SBU1) R230.1 U38.5(D2-) U38.6(NC6)
CSBU1_PORT4: J30.A8(SBU1) R244.1 U1010.1(D1+) U1010.10(NC10)
CSBU2_65986: U52.L8(C_SBU2) ; also on sheet 20
CSBU2_PORT2: J29.B8(SBU2) R231.1 U41.1(D1+) U41.10(NC10)
CSBU2_PORT4: J30.B8(SBU2) R245.1 U48.5(D2-) U48.6(NC6)
DEBUG_CTL1_82: R877.1 R1056.2 U43.E4(DEBUG_CTL1)
DEBUG_CTL1_86: R849.1 R1042.1 U52.E4(DEBUG_CTL1)
DEBUG_CTL2_82: R878.1 R1057.2 U43.D5(DEBUG_CTL2)
DEBUG_CTL2_86: R848.1 R1043.1 U52.D5(DEBUG_CTL2)
DM_DN1: J10.2(DM) U14.3(NC3) U14.12(D2+) U24.2(USB_DM_DN1)
DM_DN2: J29.A7(DN1) J29.B7(DN2) U24.10(USB_DM_DN2) U40.4(D2+) U40.7(NC7)
DM_DN3: U24.18(USB_DM_DN3) U42.22(D-)
DM_UP: U24.54(USB_DM_UP) ; also on sheet 20
DM_UP_PD: J30.A7(DN1) J30.B7(DN2) U43.L6(C_USB_TN) U43.L7(C_USB_BN) U48.2(D1-) U48.9(NC9)
DOUT: R951.1 R960.2 U42.17(DOUT)
DP_DN1: J10.3(DP) U14.4(NC4) U14.11(D2-) U24.1(USB_DP_DN1)
DP_DN2: J29.A6(DP1) J29.B6(DP2) U24.9(USB_DP_DN2) U40.5(D2-) U40.6(NC6)
DP_DN3: R1110.1 U24.17(USB_DP_DN3) U42.23(D+)
DP_MODE_LED: Q24.2(B) U52.G10(GPIO6) ; also on sheet 16 18
DP_UP: U24.53(USB_DP_UP) ; also on sheet 20
DP_UP_PD: J30.A6(DP1) J30.B6(DP2) U43.K6(C_USB_TP) U43.K7(C_USB_BP) U48.1(D1+) U48.10(NC10)
DPRX0_HPD_OUT: R1120.1 ; also on sheet 13
EN_25910: R1034.1 R1035.1 U51.16(EN#)
EN_PORT1: R1055.2 U24.36(PWRCTL1/BATEN1)
EN_PORT2: R1035.2 U24.35(PWRCTL2/BATEN2)
FLT_PORT1#: R197.2 R1054.1 U24.46(OVERCURZ1) U34.8(FAULT#)
FLT_PORT2#: R1112.2 U24.47(OVERCURZ2)
FLT_PORT2#_R: R271.1 R1112.1 U51.15(FLT#)
FLT_PORT3#: R275.1(A) U24.44(OVERCURZ3)
FLT_PORT4#: R266.1(A) U24.43(OVERCURZ4)
FUNCTION0: R957.1 R966.2 U42.5(FUNC0)
FUNCTION1: R953.1 R962.2 U42.19(FUNC1)
FUNCTION2: R952.1 R961.2 U42.18(FUNC2)
FUNCTION3: R958.1 R967.2 U42.4(FUNC3)
GANGED: R1050.2 U24.42(GANGED/SMBA2/HS_UP)
GPIO8_86: R1108.1 U52.H6(GPIO8)
GRST#: C13.1 R62.2 R1108.2 U24.50(GRST#)
HID0: R956.1 R965.2 U42.6(HID0/MS)
HID1: R955.1 R964.2 U42.7(HID1/MC)
HID2: R954.1 R963.2 U42.8(HID2/MD)
HRESET_86: C856.2 R853.2 SW2.1 SW2.2 U52.D6(HRESET)
HUB_SSTXM_P1: C72.1 J10.8(SSTXN) U14.2(NC2) U14.13(D1-)
HUB_SSTXP_P1: C62.1 J10.9(SSTXP) U14.1(NC1) U14.14(D1+)
HV_GATE1_PD: R1123.1 U43.B9(HV_GATE1)
HV_GATE2_PD: R1124.1 U43.A9(HV_GATE2)
I2C_ENABLE: R40.2 R1053.1 U24.39(SMBUSz/SS_SUPD)
I2C_IRQ_86: R847.1 U43.C1(I2C_IRQ1Z) U52.C1(I2C_IRQ1Z) ; also on sheet 19
I2C_SCL: R35.2 U24.38(SCL/SMBCLK) U1020.6(SCL)
I2C_SCL_3410: R1125.2 R1127.1 U1012.11(SCL)
I2C_SCL_MAIN: R846.1 R1042.2 R1056.1 U43.D2(I2C_SCL1) U52.D2(I2C_SCL1) U1012.29(GPIO3_4) ; also on sheet 15 19
I2C_SDA: R2.2 U24.37(SDA/SMBDAT) U1020.5(SDA)
I2C_SDA_3410: R1126.2 U1012.10(SDA) U1023.5(SDA)
I2C_SDA_MAIN: R845.1 R1043.2 R1057.1 U43.D1(I2C_SDA1) U52.D1(I2C_SDA1) U1012.30(GPIO3_3) ; also on sheet 15 19
I_MODE: R257.2(B) U53.3(I_MODE)
LDO_1V8D: C329.2 R858.1 U52.A2(LDO_1V8D)
LDO_1V8D_82: C357.2 R859.1 U43.A2(LDO_1V8D)
LDO_3V3: C323.2 C379.1 C380.1 C855.2 R843.2 R844.2 R845.2 R846.2 R847.2 R848.2 R849.2 R942.2 R943.2 R946.2 R947.2 U5.6(V+) U52.G1(LDO_3V3) U1007.8(VCC)
LDO_3V3_82: C354.2 R877.2 R878.2 U43.G1(LDO_3V3)
P2_3212_SEL: R246.1 U49.9(SEL)
PO_RESET#: R62.1 U33.1(RESET#)
POL: R1119.1 ; also on sheet 20
PORT: R935.2(B) U53.4(PORT)
PORT2_DIR: R246.2 R248.2(B) U53.11(DIR)
POWER_DETECT: Q9.1(GATE) Q13.1(GATE) Q25.2(B) R1011.1 U5.1(OUT) U43.G11(GPIO3) U52.G11(GPIO3)
PWRCTL_POL: R1052.1 U24.41(PWRCTL_POL)
PWRMGMT_EN#: R45.1 R1049.2 U24.40(FPMGT/SMBA1/SS_UP)
RESET#_3410: C891.1 R1031.2 R1032.2 U1012.9(RESET#)
SENSEN_PD: R233.2 U43.A10(SENSEN) U44.A1(S1_1) U44.B1(S1_2) U44.D1(S1_3) U44.E1(S1_4)
SENSEP_PD: R233.1 R1144.2 U43.B10(SENSEP)
SPI_CLK_86: R842.1 U1007.6(CLK) ; also on sheet 19
SPI_MISO_86: R840.1 R942.1 U1007.2(DOUT) ; also on sheet 19
SPI_MOSI_86: R839.1 U1007.5(DIN) ; also on sheet 19
SPI_SS_86: R841.1 R943.1 U1007.1(CS#) ; also on sheet 19
SSPND#: R950.1 R959.2 U42.11(SSPND#)
SSRXM_DN1: J10.5(SSRXN) U14.7(NC7) U14.8(D3-) U24.7(USB_SSRXM_DN1)
SSRXM_DN2: U24.15(USB_SSRXM_DN2) U49.8(A1N)
SSRXM_UP: U24.59(USB_SSRXM_UP) ; also on sheet 20
SSRXN1_3212: J29.B10(SSRXN1) U41.4(D2+) U41.7(NC7) U49.16(B1N)
SSRXN2_3212: J29.A10(SSRXN2) U38.2(D1-) U38.9(NC9) U49.13(C1P)
SSRXP1_3212: J29.B11(SSRXP1) U41.5(D2-) U41.6(NC6) U49.17(B1P)
SSRXP2_3212: J29.A11(SSRXP2) U38.1(D1+) U38.10(NC10) U49.12(C1N)
SSRXP_DN1: J10.6(SSRXP) U14.6(NC6) U14.9(D3+) U24.6(USB_SSRXP_DN1)
SSRXP_DN2: U24.14(USB_SSRXP_DN2) U49.7(A1P)
SSRXP_UP: U24.58(USB_SSRXP_UP) ; also on sheet 20
SSTXM_DN1: C72.2 U24.4(USB_SSTXM_DN1)
SSTXM_DN2: U24.12(USB_SSTXM_DN2) U49.4(A0N)
SSTXM_UP: U24.56(USB_SSTXM_UP) ; also on sheet 20
SSTXN1_2: C340.1 J29.A3(SSTXN1) U39.4(D2+) U39.7(NC7)
SSTXN1_3212: C340.2 U49.18(B0N)
SSTXN2_2: C343.1 J29.B3(SSTXN2) U40.2(D1-) U40.9(NC9)
SSTXN2_3212: C343.2 U49.15(C0P)
SSTXP1_2: C341.1 J29.A2(SSTXP1) U39.5(D2-) U39.6(NC6)
SSTXP1_3212: C341.2 U49.19(B0P)
SSTXP2_2: C342.1 J29.B2(SSTXP2) U40.1(D1+) U40.10(NC10)
SSTXP2_3212: C342.2 U49.14(C0N)
SSTXP_DN1: C62.2 U24.3(USB_SSTXP_DN1)
SSTXP_DN2: U24.11(USB_SSTXP_DN2) U49.3(A0P)
SSTXP_UP: U24.55(USB_SSTXP_UP) ; also on sheet 20
SUSP_3410: D821.3(K) U1012.2(SUSP)
SWD_CLK_82: U43.G4(SWD_CLK) ; also on sheet 19
SWD_CLK_86: U52.G4(SWD_CLK) ; also on sheet 19
SWD_DATA_82: U43.F4(SWD_DATA) ; also on sheet 19
SWD_DATA_86: U52.F4(SWD_DATA) ; also on sheet 19
TN_FTDI_82_R: R1058.2 R1114.2 U43.K5(USB_RP_N)
TP_FTDI_82_R: R1059.2 R1113.2 U43.L5(USB_RP_P)
UART_RX_86: R946.1 U43.E2(UART_TX) U52.F2(UART_RX) ; also on sheet 19
UART_TX_86: R947.1 U43.F2(UART_RX) U52.E2(UART_TX) ; also on sheet 19
USB_R1: R20.1 U24.64(USB_R1)
USB_RN_82: R1058.1 R1077.1
USB_RP_82: R1059.1 R1078.1
USB_TN_FTDI: U52.K5(USB_RP_N) ; also on sheet 19
USB_TN_FTDI_82: R1114.1 ; also on sheet 19
USB_TP_FTDI: U52.L5(USB_RP_P) ; also on sheet 19
USB_TP_FTDI_82: R1113.1 ; also on sheet 19
USB_VBUS_UP: R32.2 R39.1 U24.48(USB_VBUS)
VREGEN_3410: D821.1(A) R1032.1 R1139.1 U1012.1(VREGEN)
XI: C10.1 R17.2 U24.62(XI) Y2.3
XO: C9.1 R17.1 U24.61(XO) Y2.1
N16777083: C290.1 R173.1 U1.6(COMP)
N16777133: C291.1 U1.4(SS)
N16777225: C292.1 U1.1(BOOT)
N16777234: C292.2 D7.1(CATHODE) L24.1 U1.8(PH)
N16777391: R174.2 R175.1 U1.5(VSENSE)
N16778410: R176.2 R178.1 R179.1
N16778432: R178.2 U2.2(EN)
N16778697: C294.1 R184.1 U2.18(VREG)
N16778752: R180.1 U2.21(TRIP)
N16779274: C299.2 L25.1 R183.1 U2.6(LL1) U2.7(LL2) U2.8(LL3) U2.9(LL4) U2.10(LL5) U2.11(LL6)
N16779338: C299.1 U2.4(VBST)
N16779519: C298.2 C300.1 R183.2
N16779532: C298.1 R181.2 R182.1 U2.1(VFB)
N16779659: R184.2 U2.3(PGOOD)
N16779668: R177.1 U2.20(MODE)
N16782094: C306.1 R185.1 U3.6(COMP)
N16782107: C308.1 U3.4(SS)
N16782117: C307.1 R185.2
N16782233: C311.1 U3.1(BOOT)
N16782257: C311.2 D8.1(CATHODE) L26.1 U3.8(PH)
N16782404: R186.1 R187.2 U3.5(VSENSE)
N16785382: D814.2(ANODE) D831.2(ANODE) J31.1(+IN) J31.2(GND) J31.3(GND#3)
N16790811: R157.1(A) SW3.1 SW3.2 U33.2(PB_RESET#)
N16793035: R196.1 U34.6(ILIM)
N16794879: R268.2 U34.4(EN)
N16794977: L28.2 U34.1(SW)
N16795009: R1055.1 R1109.2 U34.7(ENUSB)
N16799162: C322.2 U52.E1(LDO_BMC)
N16799357: C327.2 U52.K1(LDO_1V8A)
N16800849: C381.2 U52.H2(VOUT_3V3)
N16804911: R202.2 U52.F1(I2C_ADDR)
N16804916: R201.2 U52.G2(R_OSC)
N16808761: Q26.1(E) R32.1 R218.2
N16810808: C344.1 C863.1 C864.1 C865.1 FB605.1 J29.A4(VBUS1) J29.A9(VBUS2) J29.B4(VBUS3) J29.B9(VBUS4)
N16813222: C348.2 C349.2 R862.2 U43.A6(PP_HV3) U43.A7(PP_HV2) U43.A8(PP_HV1) U43.B7(PP_HV4)
N16813358: C350.2 FB14.1 U43.H11(VBUS1) U43.J10(VBUS2) U43.J11(VBUS3) U43.K11(VBUS4) U44.A2(S2_1) U44.B2(S2_2) U44.D2(S2_3) U44.E2(S2_4)
N16813564: R236.2 U43.G2(R_OSC)
N16813774: C353.2 U43.E1(LDO_BMC)
N16813818: C355.2 U43.K1(LDO_1V8A)
N16813859: C375.2 U43.H2(VOUT_3V3)
N16816568: R1124.2 U44.C2(G2)
N16822441: R262.2 U51.7(ILIM)
N16822446: R262.1 R263.2
N16829090: R1036.2 U5.4(IN-)
N16829289: R264.2 R265.1 U5.3(IN+)
N16836617: R839.2 U52.B4(SPI_MOSI)
N16836619: R840.2 U52.A4(SPI_MISO)
N16836621: R841.2 U52.B3(SPI_SSZ)
N16836642: R842.2 U52.A3(SPI_CLK)
N16838204: R196.2 R269.1
N16842659: R272.1 U53.5(VBUS_DET)
N16843562: C384.1 R273.1 U42.12(XTI) Y3.1
N16843567: C385.1 R273.2 U42.13(XTO) Y3.3
N16843866: R274.1 U42.15(DT)
N16844998: C389.1 C391.1 R278.2 U42.29(VOUT_R)
N16845005: C390.1 C392.1 R279.2 U42.28(VOUT_L)
N16845082: C388.1 U42.32(VCOM)
N16845408: C391.2 J16.1 R280.2
N16845429: C392.2 J16.2 R281.2
N16845509: C389.2 R276.2
N16845512: C390.2 R277.2
N16847122: C396.2 U43.H7(SS)
N16848630: C399.2 U52.H7(SS)
N16901755: R1044.2 U52.K6(C_USB_TP) U52.K7(C_USB_BP)
N16901758: R1045.2 U52.L6(C_USB_TN) U52.L7(C_USB_BN)
N16951210: R843.1 U1007.3(WP#)
N16951303: R844.1 U1007.7(HOLD#)
N16952885: R854.1 SW2.3 SW2.4
N16965459: R237.2 U43.F1(I2C_ADDR)
N16973659: Q26.2(B) R219.1 R1047.2
N17068763: R936.2 R937.1 U3.3(EN)
N17082063: R971.1 SW503.3 SW503.4
N17164542: Q9.3(DRAIN) Q23.2(B) R1007.2
N17165224: D824.2(ANODE) R195.2
N17165327: D824.1(CATHODE) Q27.3(C)
N17165346: Q27.2(B) R1008.2 R1054.2
N17165771: Q29.2(B) R1011.2
N17165775: D825.1(CATHODE) Q29.3(C)
N17165871: D826.2(ANODE) R1010.1
N17166161: Q13.3(DRAIN) Q28.2(B) R1012.1
N17179025: C887.1 C888.1 U1012.4(VDD1V8)
N17179646: R1029.2 U1012.12(WAKEUP#)
N17185126: R1028.2 U1012.23(TEST0) U1012.24(TEST1)
N17185162: R1030.2 U1012.5(PUR)
N17185171: R1030.1 R1061.2 R1078.2 U1012.6(DP)
N17185289: C889.1 U1012.27(X1) Y503.1
N17185336: C890.1 U1012.26(X2) Y503.3
N17209365: D823.2(ANODE) R1005.2
N17209368: D823.1(CATHODE) Q25.3(C)
N17209381: D822.2(ANODE) R1006.2
N17209384: D822.1(CATHODE) Q23.3(C)
N17209650: D826.1(CATHODE) Q28.3(C)
N17221537: D825.2(ANODE) R1009.1
N17276636: R1036.1 U5.5(REF)
N17285021: R1060.2 R1077.2 U1012.7(DM)
N17301163: D820.1(CATHODE) Q24.3(C)
N17301291: D820.2(ANODE) R1027.1
N17345873: R1085.1 U1020.3(A2)
N17345880: R1086.1 U1020.2(A1)
N17346356: R1088.1 U1020.7(WP)
N17507127: R1117.2 U52.B2(GPIO0)
N17507194: R1118.2 U52.C2(GPIO1)
N17507240: R1119.2 U52.D10(GPIO2)
N17507300: R1120.2 U52.C10(GPIO4_HPD)
N17507456: R1122.2 U52.E10(GPIO5_HPD)
N17509031: R1123.2 U44.C1(G1)
N17510585: R1127.2 U1023.6(SCL)
N17560224: R1062.1 U1023.7(WP)
N17560831: R1131.1 U1023.1(A0) U1023.2(A1) U1023.3(A2)
N17571456: R1121.2 U52.K2(DEBUG2)
N17594321: R1140.2 R1143.1 U42.16(PSEL)
N17594324: R1141.2 R1142.1 U42.9(FSEL)
N17641276: C289.1 R173.2

Not connected (* = marked no-connect by the designer): D821 2(NC)*; J30 A2(SSTXP1)* A3(SSTXN1)* A10(SSRXN2)* A11(SSRXP2)* B2(SSTXP2)* B3(SSTXN2)* B10(SSRXN1)* B11(SSRXP1)*; U1 3(EN)*; U2 22(RF)*; U24 19(USB_SSTXP_DN3)* 20(USB_SSTXM_DN3)* 22(USB_SSRXP_DN3)* 23(USB_SSRXM_DN3)* 26(USB_SSTXP_DN4)* 27(USB_SSTXM_DN4)* 29(USB_SSRXP_DN4)* 30(USB_SSRXM_DN4)* 32(PWRCTL4/BATEN4)* 33(PWRCTL3/BATEN3)* 49(TEST)* 60(NC)*; U39 2(D1-)* 9(NC9)*; U41 2(D1-)* 9(NC9)*; U42 14(CK)*; U43 A3(SPI_CLK)* A4(SPI_MISO)* A5(I2C_SDA2)* B2(GPIO0)* B3(SPI_SSZ)* B4(SPI_MOSI)* B5(I2C_SCL2)* B6(I2C_IRQ2Z)* C2(GPIO1)* C10(GPIO4_HPD)* D7(GPIO7)* D10(GPIO2)* E10(GPIO5_HPD)* E11(MRESET)* F11(RESET#)* G10(GPIO6)* H6(GPIO8)* J1(AUX_P)* J2(AUX_N)* K2(DEBUG2)* K3(DEBUG4)* K4(LSX_P2R)* K8(C_SBU1)* L2(DEBUG1)* L3(DEBUG3)* L4(LSX_R2P)* L8(C_SBU2)* L11(NC)*; U49 1(NC1)* 10(NC10)*; U52 A9(NCA9)* B6(NCB6)* B9(NCB9)* D7(GPIO7)* E11(MRESET)* F11(RESET#)* K3(DEBUG4)* K4(NCK4)* L2(DEBUG1)* L11(NC)*; U1010 2(D1-)* 5(D2-)* 6(NC6)* 9(NC9)*; U1012 13(CTS#)* 14(DSR#)* 15(DCD#)* 16(RI)* 17(SIN)* 19(SOUT)* 20(RTS#)* 21(DTR#)* 22(CLKOUT)*; U1020 1(NC)*

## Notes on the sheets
sheet 1
- 1- PLACE C916 C917 ANY WHERE ON THE BOARD
- 2- KEEP C2, C3, C7, C8 CAPS CLOSE TO CONNECTOR LET RESISTORS SHARE PADS
- 3- KEEP ESD CLOSE TO CONNECTOR
- 4- THESE CONNECTIONS ARE FOR FLOW THROUGH ROUTING
- 5- DP MODE LED PLACE NEAR DP/HDMI
- 6- KEEP C340, C341, C342, C343 CAPS CLOSE TO CONNECTOR LET RESISTORS SHARE PADS
- 7- THESE CONNECTIONS ARE FOR FLOW THROUGH ROUTING
- 8- C291 AND C192 MUST BE 5.4mm TALL
- 9- PAD SHARING R1058 AND R1114, R1059 AND R1113
- 10- Place R1077 and R1078 as close as possible to R1060 and R1061
- 11- PAD SHARING R873 AND R875, R874 AND 876
- 12- Pad sharing with R1060 and R1061 on page 12
sheet 2
- TEXAS INSTRUMENTS
  TIDA-01243  TYPE-C MINI DOCK BOARD
- REV B - FIX REV 1 ISSUES
- REV A - INITIAL RELEASE
sheet 3
- BOARD POWER
- +3.3V @ 3A
- HEIGHT=3.1mm
- +5V @7A
- 20V
- 20V
- Note #1
sheet 4
- BOARD POWER - 2
- +1.2V @ 3A
- POWER LEDS
- 42V@10A
- 25V 5A
sheet 5
- TPS65986
- NOTE #5
- FROM MST HUB
- NOTE #12
- TO TUSB8041
- 8Mb SPI FLASH
sheet 6
- TUSB 4 PORT USB3.0 HUB
- DOWNSTREAM PORTS
- USB 3
- FROM HD3SS460
- USB TYPE C
- AUDIO
- (USB2 ONLY ON THIS PORT)
- SIGNAL
- DEFINATION
- I2C_ENABLE
- HIGH=I2C ENABLED
- USB TYPE C CHARGING
- (NO DATA ON THIS PORT)
- PWRMGMT_EN#
- LOW=PWR MANAGEMENT ENABLED
- PWRCTL_POL
- HIGH=ACTIVE HIGH POLARITY
  (INTERNAL PULL-UP)
- GANGED
- LOW=INDIVIDUAL PORT CONTROL
- AUTO_EN
- LOW=AUTO MODE ENABLED
- RESET SWITCH FOR DEBUG
sheet 7
- DOWNSTREAM USB PORT 1 USB3
- NOTE #3
- PORT 1
- SINGLE USB 3.0 CONNECTOR
- PORT 1 LED
- NOTE #3
- TO HDMI
- 16V
- SET CURRENT LIMIT TO 1.4A
- RLIM = 20.5K
sheet 8
- DOWNSTREAM USB C PORT 2
- Type C Connector
- TypeC Connector Pin Mapping
- GND
- A1
- B12
- GND
- SSTXP1
- SSRXP1
- SSTXP2
- A2
- B11
- SSRXP2
- SSTXN1
- A3
- B10
- SSRXN1
- TO TUSB8041
- SSTXN2
- SSRXN1
- VBUS
- VBUS
- A4
- B9
- CC1
- A5
- B8
- SBU2
- DP1
- DN2
- A6
- B7
- DN1
- A7
- B6
- DP2
- 55K LIMITS CURRENT
  TO 3.6AMPS
- SBU1
- CC2
- A8
- B5
- VBUS
- A9
- B4
- VBUS
- SSRXN2
- SSTXN2
- NOTE #6
- SSRXN1
- A10
- B3
- SSTXN1
- SSRXP2
- B2
- SSTXP2
- SSRXP1
- A11
- SSTXP1
- GND
- A12
- B1
- GND
- NOTE: ALL DIFF PAIRS ARE
  ROUTED 85 TO 90 OHMS
  DIFFERENTIAL AND 50 OHMS
  COMMON MODE. ALL OTHER
  TRACES ARE 50 OHM.
- NOTE #3
- PORT 2 LEDS
- NOTE #7
sheet 9
- DOWNSTREAM USB C PORT 2
- TO/FROM CONNECTOR
- TO/FROM TUSB8041
- INTENTIONALLY SWAPPED
- FROM TUSB321 DONGLE SCHEMATIC
- I_MODE = 10K (3A)
- PORT = 1, DFP MODE
sheet 10
- USB AUDIO PORT 3
- NOTE #8
- HEADPHONE JACK
- FROM TUSB8041
sheet 11
- PORT 4 - TPS65982
- NOTE #9
sheet 12
- PORT 4 - TYPE C PD
  ONLY USED TO SUPPLY POWER
- NOTE #10
- Type C Connector
- TypeC Connector Pin Mapping
- GND
- A1
- B12
- GND
- TPS65986 BB option
- SSTXP1
- SSRXP1
- SSTXP2
- A2
- B11
- SSRXP2
- SSTXN1
- A3
- B10
- SSRXN1
- SSTXN2
- SSRXN1
- VBUS
- VBUS
- A4
- B9
- CC1
- A5
- B8
- SBU2
- DP1
- DN2
- A6
- B7
- DN1
- A7
- B6
- DP2
- SBU1
- A8
- B5
- CC2
- VBUS
- VBUS
- A9
- B4
- SSRXN1
- SSRXN2
- A10
- B3
- SSTXN1
- SSTXN2
- SSRXP2
- SSTXP2
- SSRXP1
- A11
- B2
- SSTXP1
- GND
- A12
- B1
- GND
- NOTE: ALL DIFF PAIRS ARE
  ROUTED 85 TO 90 OHMS
  DIFFERENTIAL AND 50 OHMS
  COMMON MODE. ALL OTHER
  TRACES ARE 50 OHM.
- NOTE #3
- NOTE #7
